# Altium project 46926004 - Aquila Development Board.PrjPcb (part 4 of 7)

## Sheet 360_Ethernet2.SchDoc: Aquila Development Board
size A3; Organization: Toradex Solutions Inc.; Address1: 6415 Northwest Drive; Address2: Mississauga, ON, L4V 1X1; Address3: Canada; SheetNumber: 20; SheetTotal: 34
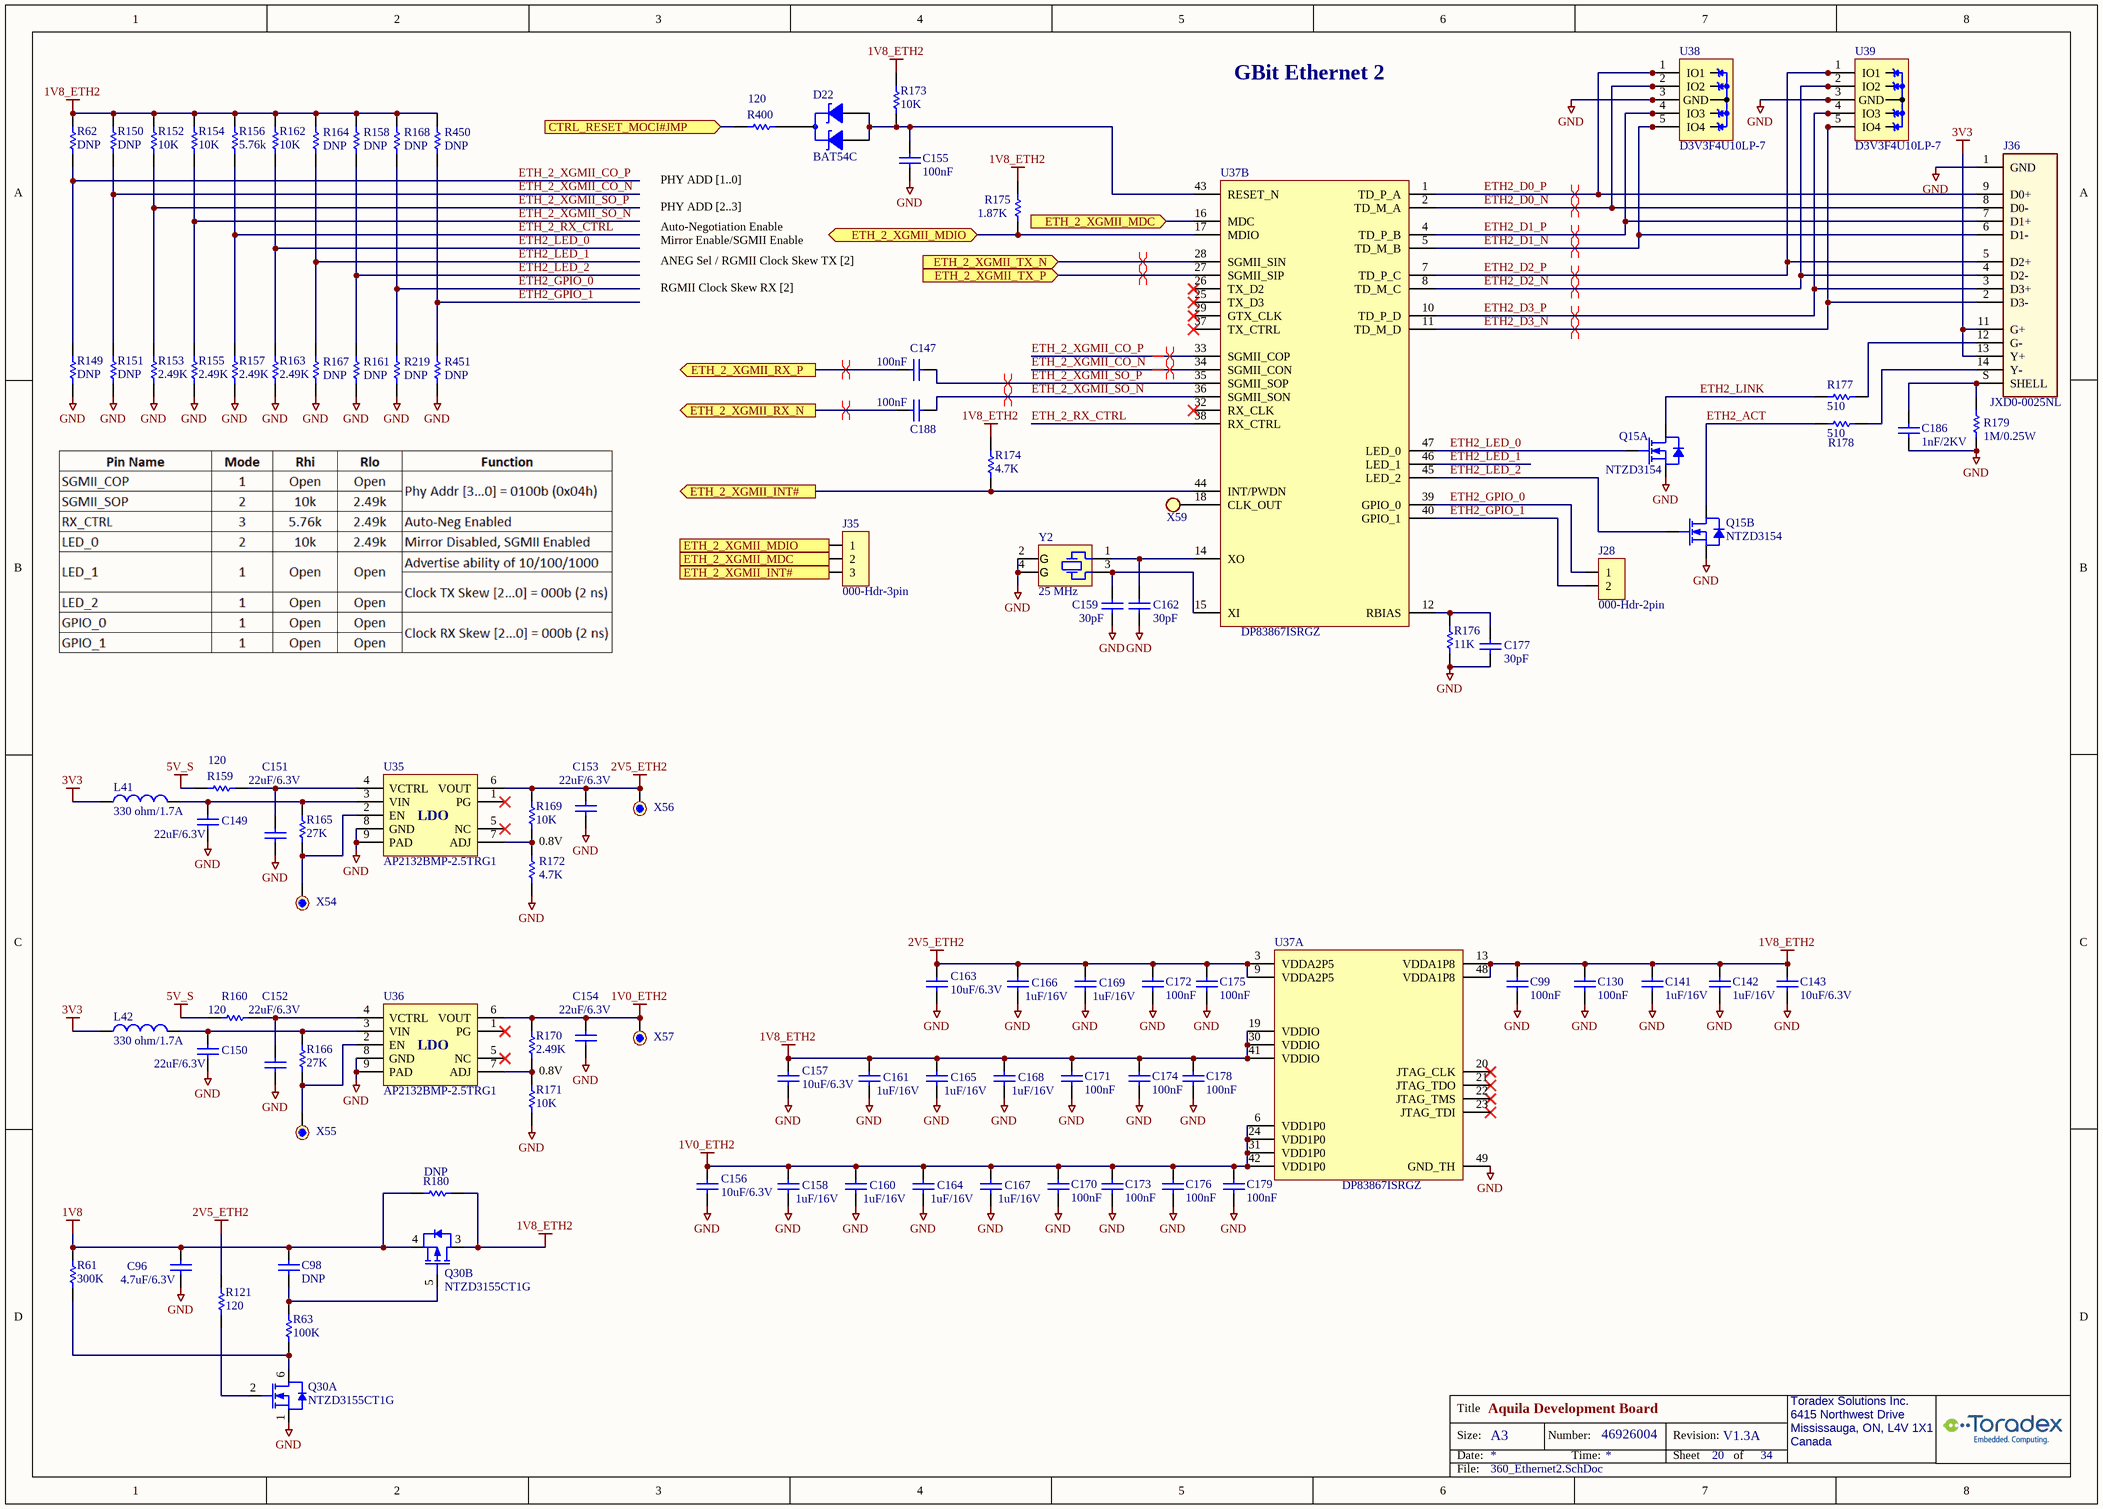
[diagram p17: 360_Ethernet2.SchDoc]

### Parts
C96  value 4.7uF/6.3V  [C0402_CAPC1005L]  (hidden comment: 0354-Cap-0402-4.7uF/6.3V)
C98  value DNP  [C/0603]  (hidden comment: 0000-Cap-0603-DNP)
C99  100nF  [C0402_CAPC1005L]
C130  100nF  [C0402_CAPC1005L]
C141  value 1uF/16V  [C0402_CAPC1005L]  (hidden comment: 1644-Cap-0402-1uF/16V)
C142  value 1uF/16V  [C0402_CAPC1005L]  (hidden comment: 1644-Cap-0402-1uF/16V)
C143  value 10uF/6.3V  [C0402_CAPC1005L]  (hidden comment: 1646-Cap-0402-10uF/6.3V)
C147  100nF  [C0402_CAPC1005L]
C149  22uF/6.3V  [C0402_CAPC1005L]
C150  22uF/6.3V  [C0402_CAPC1005L]
C151  22uF/6.3V  [C0402_CAPC1005L]
C152  22uF/6.3V  [C0402_CAPC1005L]
C153  22uF/6.3V  [C0402_CAPC1005L]
C154  22uF/6.3V  [C0402_CAPC1005L]
C155  100nF  [C0402_CAPC1005L]
C156  value 10uF/6.3V  [C0402_CAPC1005L]  (hidden comment: 1646-Cap-0402-10uF/6.3V)
C157  value 10uF/6.3V  [C0402_CAPC1005L]  (hidden comment: 1646-Cap-0402-10uF/6.3V)
C158  value 1uF/16V  [C0402_CAPC1005L]  (hidden comment: 1644-Cap-0402-1uF/16V)
C159  value 30pF  [C0402_CAPC1005L]  (hidden comment: 1554-Cap-0402-30pF)
C160  value 1uF/16V  [C0402_CAPC1005L]  (hidden comment: 1644-Cap-0402-1uF/16V)
C161  value 1uF/16V  [C0402_CAPC1005L]  (hidden comment: 1644-Cap-0402-1uF/16V)
C162  value 30pF  [C0402_CAPC1005L]  (hidden comment: 1554-Cap-0402-30pF)
C163  value 10uF/6.3V  [C0402_CAPC1005L]  (hidden comment: 1646-Cap-0402-10uF/6.3V)
C164  value 1uF/16V  [C0402_CAPC1005L]  (hidden comment: 1644-Cap-0402-1uF/16V)
C165  value 1uF/16V  [C0402_CAPC1005L]  (hidden comment: 1644-Cap-0402-1uF/16V)
C166  value 1uF/16V  [C0402_CAPC1005L]  (hidden comment: 1644-Cap-0402-1uF/16V)
C167  value 1uF/16V  [C0402_CAPC1005L]  (hidden comment: 1644-Cap-0402-1uF/16V)
C168  value 1uF/16V  [C0402_CAPC1005L]  (hidden comment: 1644-Cap-0402-1uF/16V)
C169  value 1uF/16V  [C0402_CAPC1005L]  (hidden comment: 1644-Cap-0402-1uF/16V)
C170  100nF  [C0402_CAPC1005L]
C171  100nF  [C0402_CAPC1005L]
C172  100nF  [C0402_CAPC1005L]
C173  100nF  [C0402_CAPC1005L]
C174  100nF  [C0402_CAPC1005L]
C175  100nF  [C0402_CAPC1005L]
C176  100nF  [C0402_CAPC1005L]
C177  value 30pF  [C0402_CAPC1005L]  (hidden comment: 1554-Cap-0402-30pF)
C178  100nF  [C0402_CAPC1005L]
C179  100nF  [C0402_CAPC1005L]
C186  value 1nF/2KV  [C/1206]  (hidden comment: 0567-Cap-1206-1nF/2KV)
C188  100nF  [C0402_CAPC1005L]
D22  BAT54C  [SOT23_M]
J28  000-Hdr-2pin  [HDR1X2]  (no BOM)
J35  000-Hdr-3pin  [HDR1X3]  (no BOM)
J36  JXD0-0025NL  [PULSE_JXD0-0025NL]
L41  value 330 ohm/1.7A  [C/0603]  (hidden comment: 0405-Fer-0603-330ohm/1.7A)
L42  value 330 ohm/1.7A  [C/0603]  (hidden comment: 0405-Fer-0603-330ohm/1.7A)
Q15  NTZD3154  [SOT563]  (parts A,B of 2)
Q30  NTZD3155CT1G  [SOTFL50P160X60-6N]  (parts A,B of 2)
R61  value 300K  [R/0603]  (hidden comment: 0176-Res-0603-300K)
R62  value DNP  [R0402_RESC1005L]  (hidden comment: 0000-Res-0402-DNP)
R63  value 100K  [R0402_RESC1005L]  (hidden comment: 1977-Res-0402-100K)
R121  value 120  [R0402_RESC1005L]  (hidden comment: 1552-Res-0402-120)
R149  value DNP  [R0402_RESC1005L]  (hidden comment: 0000-Res-0402-DNP)
R150  value DNP  [R0402_RESC1005L]  (hidden comment: 0000-Res-0402-DNP)
R151  value DNP  [R0402_RESC1005L]  (hidden comment: 0000-Res-0402-DNP)
R152  value 10K  [R0402_RESC1005L]  (hidden comment: 1572-Res-0402-10K)
R153  value 2.49K  [R0402_RESC1005L]  (hidden comment: 2313-Res-0402-2.49K)
R154  value 10K  [R0402_RESC1005L]  (hidden comment: 1572-Res-0402-10K)
R155  value 2.49K  [R0402_RESC1005L]  (hidden comment: 2313-Res-0402-2.49K)
R156  value 5.76k  [R0402_RESC1005L]  (hidden comment: 2077-Res-0402-5.76K)
R157  value 2.49K  [R0402_RESC1005L]  (hidden comment: 2313-Res-0402-2.49K)
R158  value DNP  [R0402_RESC1005L]  (hidden comment: 0000-Res-0402-DNP)
R159  value 120  [R0402_RESC1005L]  (hidden comment: 1552-Res-0402-120)
R160  value 120  [R0402_RESC1005L]  (hidden comment: 1552-Res-0402-120)
R161  value DNP  [R0402_RESC1005L]  (hidden comment: 0000-Res-0402-DNP)
R162  value 10K  [R0402_RESC1005L]  (hidden comment: 1572-Res-0402-10K)
R163  value 2.49K  [R0402_RESC1005L]  (hidden comment: 2313-Res-0402-2.49K)
R164  value DNP  [R0402_RESC1005L]  (hidden comment: 0000-Res-0402-DNP)
R165  value 27K  [R0402_RESC1005L]  (hidden comment: 1538-Res-0402-27k)
R166  value 27K  [R0402_RESC1005L]  (hidden comment: 1538-Res-0402-27k)
R167  value DNP  [R0402_RESC1005L]  (hidden comment: 0000-Res-0402-DNP)
R168  value DNP  [R0402_RESC1005L]  (hidden comment: 0000-Res-0402-DNP)
R169  value 10K  [R0402_RESC1005L]  (hidden comment: 1572-Res-0402-10K)
R170  value 2.49K  [R0402_RESC1005L]  (hidden comment: 2313-Res-0402-2.49K)
R171  value 10K  [R0402_RESC1005L]  (hidden comment: 1572-Res-0402-10K)
R172  value 4.7K  [R0402_RESC1005L]  (hidden comment: 2233-Res-0402-4.7K)
R173  value 10K  [R0402_RESC1005L]  (hidden comment: 1572-Res-0402-10K)
R174  value 4.7K  [R0402_RESC1005L]  (hidden comment: 2233-Res-0402-4.7K)
R175  value 1.87K  [R0402_RESC1005L]  (hidden comment: 1536-Res-0402-1.87K)
R176  value 11K  [R0402_RESC1005L]  (hidden comment: 2527-Res-0402-11K)
R177  value 510  [R/0603]  (hidden comment: 0043-Res-0603-510ohm)
R178  value 510  [R/0603]  (hidden comment: 0043-Res-0603-510ohm)
R179  value 1M/0.25W  [R/1206]  (hidden comment: 1860-Res-1206-1M-5%-0.25W)
R180  value DNP  [R/0603]  (hidden comment: 0000-Res-0603-DNP)
R219  value DNP  [R0402_RESC1005L]  (hidden comment: 0000-Res-0402-DNP)
R400  value 120  [R0402_RESC1005L]  (hidden comment: 1552-Res-0402-120)
R450  value DNP  [R0402_RESC1005L]  (hidden comment: 0000-Res-0402-DNP)
R451  value DNP  [R0402_RESC1005L]  (hidden comment: 0000-Res-0402-DNP)
U35  AP2132BMP-2.5TRG1  [SOP-9 TP_ALT]
U36  AP2132BMP-2.5TRG1  [SOP-9 TP_ALT]
U37  DP83867ISRGZ  [RGZ0048B]  (parts A,B of 2)
U38  D3V3F4U10LP-7  [10-UFDFN]
U39  D3V3F4U10LP-7  [10-UFDFN]
X54  000-TestPoint  [TestPoint_1]  (value not drawn)
X55  000-TestPoint  [TestPoint_1]  (value not drawn)
X56  000-TestPoint  [TestPoint_1]  (value not drawn)
X57  000-TestPoint  [TestPoint_1]  (value not drawn)
X59  000-TestPoint2  [TestPoint_3]  (value not drawn)
Y2  value 25 MHz  [XTAL_CX3225]  (hidden comment: 0987-Xtal 25MHz 3.2x2.5mm)

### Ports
CTRL_RESET_MOCI#JMP (in), ETH_2_XGMII_INT#, ETH_2_XGMII_INT# (out), ETH_2_XGMII_MDC, ETH_2_XGMII_MDC (in), ETH_2_XGMII_MDIO, ETH_2_XGMII_MDIO (bidir), ETH_2_XGMII_RX_N (out), ETH_2_XGMII_RX_P (out), ETH_2_XGMII_TX_N (in), ETH_2_XGMII_TX_P (in)

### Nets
1V0_ETH2: C154.2 C156.2 C158.2 C160.2 C164.2 C167.2 C170.1 C173.1 C176.1 C179.1 R170.2 U36.6(VOUT) U37.6(VDD1P0) U37.24(VDD1P0) U37.31(VDD1P0) U37.42(VDD1P0) X57.1
1V8: C96.2 C98.1 Q30.4(S) R61.1 R180.2
1V8_ETH2: C99.1 C130.1 C141.2 C142.2 C143.2 C157.2 C161.2 C165.2 C168.2 C171.1 C174.1 C178.1 Q30.3(D) R62.2 R150.2 R152.2 R154.2 R156.1 R158.2 R162.2 R164.2 R168.2 R173.2 R174.2 R175.2 R180.1 R450.2 U37.13(VDDA1P8) U37.19(VDDIO) U37.30(VDDIO) U37.41(VDDIO) U37.48(VDDA1P8)
2V5_ETH2: C153.2 C163.2 C166.2 C169.2 C172.1 C175.1 R121.2 R169.2 U35.6(VOUT) U37.3(VDDA2P5) U37.9(VDDA2P5) X56.1
3V3: J36.11(G+) J36.13(Y+) L41.2 L42.2
5V_S: R159.2 R160.2
GND: C96.1 C99.2 C130.2 C141.1 C142.1 C143.1 C149.1 C150.1 C151.1 C152.1 C153.1 C154.1 C155.2 C156.1 C157.1 C158.1 C159.2 C160.1 C161.1 C162.2 C163.1 C164.1 C165.1 C166.1 C167.1 C168.1 C169.1 C170.2 C171.2 C172.2 C173.2 C174.2 C175.2 C176.2 C177.2 C178.2 C179.2 C186.1 J36.1(GND) Q15.1(S) Q15.4(S) Q30.1(S) R149.1 R151.1 R153.1 R155.1 R157.1 R161.1 R163.1 R167.1 R171.1 R172.1 R176.1 R179.2 R219.1 R451.1 U35.8(GND) U35.9(PAD) U36.8(GND) U36.9(PAD) U37.49(GND_TH) U38.3(GND) U38.8(GND) U39.3(GND) U39.8(GND) Y2.2(GND) Y2.4(GND)
CTRL_RESET_MOCI#JMP: R400.2 ; port CTRL_RESET_MOCI#JMP
ETH2_ACT: Q15.3(D) R178.1
ETH2_D0_N: J36.8(D0-) U37.2(TD_M_A) U38.2(IO2) U38.9(NC)
ETH2_D0_P: J36.9(D0+) U37.1(TD_P_A) U38.1(IO1) U38.10(NC)
ETH2_D1_N: J36.6(D1-) U37.5(TD_M_B) U38.5(IO4) U38.6(NC)
ETH2_D1_P: J36.7(D1+) U37.4(TD_P_B) U38.4(IO3) U38.7(NC)
ETH2_D2_N: J36.4(D2-) U37.8(TD_M_C) U39.2(IO2) U39.9(NC)
ETH2_D2_P: J36.5(D2+) U37.7(TD_P_C) U39.1(IO1) U39.10(NC)
ETH2_D3_N: J36.2(D3-) U37.11(TD_M_D) U39.5(IO4) U39.6(NC)
ETH2_D3_P: J36.3(D3+) U37.10(TD_P_D) U39.4(IO3) U39.7(NC)
ETH2_GPIO_0: J28.1 R168.1 R219.2 U37.39(GPIO_0)
ETH2_GPIO_1: J28.2 R450.1 R451.2 U37.40(GPIO_1)
ETH2_LED_0: Q15.2(G) R162.1 R163.2 U37.47(LED_0)
ETH2_LED_1: R164.1 R167.2 U37.46(LED_1)
ETH2_LED_2: Q15.5(G) R158.1 R161.2 U37.45(LED_2)
ETH2_LINK: Q15.6(D) R177.1
ETH_2_RX_CTRL: R156.2 R157.2 U37.38(RX_CTRL)
ETH_2_XGMII_CO_N: R150.1 R151.2 U37.34(SGMII_CON)
ETH_2_XGMII_CO_P: R62.1 R149.2 U37.33(SGMII_COP)
ETH_2_XGMII_INT#: J35.3 R174.1 U37.44(INT/PWDN) ; port ETH_2_XGMII_INT#
ETH_2_XGMII_MDC: J35.2 U37.16(MDC) ; port ETH_2_XGMII_MDC
ETH_2_XGMII_MDIO: J35.1 R175.1 U37.17(MDIO) ; port ETH_2_XGMII_MDIO
ETH_2_XGMII_RX_N: C188.2 ; port ETH_2_XGMII_RX_N
ETH_2_XGMII_RX_P: C147.2 ; port ETH_2_XGMII_RX_P
ETH_2_XGMII_SO_N: C188.1 R154.1 R155.2 U37.36(SGMII_SON)
ETH_2_XGMII_SO_P: C147.1 R152.1 R153.2 U37.35(SGMII_SOP)
ETH_2_XGMII_TX_N: U37.28(SGMII_SIN) ; port ETH_2_XGMII_TX_N
ETH_2_XGMII_TX_P: U37.27(SGMII_SIP) ; port ETH_2_XGMII_TX_P
NetC98_2: C98.2 Q30.5(G) R63.1
NetC149_2: C149.2 L41.1 R165.1 U35.3(VIN)
NetC150_2: C150.2 L42.1 R166.1 U36.3(VIN)
NetC151_2: C151.2 R159.1 U35.4(VCTRL)
NetC152_2: C152.2 R160.1 U36.4(VCTRL)
NetC155_1: C155.1 D22.1(A1) D22.2(A2) R173.1 U37.43(RESET_N)
NetC159_1: C159.1 U37.15(XI) Y2.3
NetC162_1: C162.1 U37.14(XO) Y2.1
NetC177_1: C177.1 R176.2 U37.12(RBIAS)
NetC186_2: C186.2 J36.S(SHELL) R179.1
NetD22_3: D22.3(K) R400.1
NetJ36_12: J36.12(G-) R177.2
NetJ36_14: J36.14(Y-) R178.2
NetQ30_2: Q30.2(G) R121.1
NetQ30_6: Q30.6(D) R61.2 R63.2
NetR165_2: R165.2 U35.2(EN) X54.1
NetR166_2: R166.2 U36.2(EN) X55.1
NetR169_1: R169.1 R172.2 U35.7(ADJ)
NetR170_1: R170.1 R171.2 U36.7(ADJ)
NetU37_18: U37.18(CLK_OUT) X59.1

Not connected (* = marked no-connect by the designer): U35 1(PG)* 5(NC)*; U36 1(PG)* 5(NC)*; U37 20(JTAG_CLK)* 21(JTAG_TDO)* 22(JTAG_TMS)* 23(JTAG_TDI)* 25(TX_D3)* 26(TX_D2)* 29(GTX_CLK)* 32(RX_CLK)* 37(TX_CTRL)*

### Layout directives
differential pair; differential pair class ETH2: ETH2_D0_N, ETH2_D0_P, ETH2_D1_N, ETH2_D1_P, ETH2_D2_N, ETH2_D2_P, ETH2_D3_N, ETH2_D3_P
differential pair; differential pair class XGMII: ETH_2_XGMII_RX_N, ETH_2_XGMII_RX_P, ETH_2_XGMII_TX_N, ETH_2_XGMII_TX_P
differential pair; differential pair class XGMII_PHY: ETH_2_XGMII_CO_N, ETH_2_XGMII_CO_P, ETH_2_XGMII_SO_N, ETH_2_XGMII_SO_P

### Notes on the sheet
- GBit Ethernet 2
- (near R400) PHY ADD [1..0]
- PHY ADD [2..3]
- Auto-Negotiation Enable
- Mirror Enable/SGMII Enable
- ANEG Sel / RGMII Clock Skew TX [2]
- RGMII Clock Skew RX [2]
- 0.8V

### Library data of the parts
C96 = 0354-Cap-0402-4.7uF/6.3V: (-55 to 85 DegC) CAP CER 4.7UF 6.3V 20% X5R 0402; Mfr: Murata Electronics North America; MfrNo: GRM155R60J475ME87D; Alt: 1276-1483-1-ND; Alt2: 490-5915-1-ND; PN: 354
C98 = 0000-Cap-0603-DNP: Cap 0603 DNP
C99 C130 C147 C155 C170-C176 C178 C179 C188 = 1566-Cap-0402-100nF/50V: (-55 to 125 DegC AEC) Cap Ceramic 0.1uF 50V X7R 10% 0402; MfrNo: GRT155R71H104KE01D; Mfr: Murata; Alt: CL05B104KB54PNC,GCM155R71H104ME02D,GCM155R71H104KE02D,GCM155R71H104KE02J; PN: 1566
C141 C142 C158 C160 C161 C164-C169 = 1644-Cap-0402-1uF/16V: (-55 to 85 DegC) CAP CER 1UF 16V 20% X5R 0402; Mfr: Murata; MfrNo: GRM155R61C105MA12D; PN: 1644; Alt: GRM155R61C105KA12D,CL05A105KO5NNNC
C143 C156 C157 C163 = 1646-Cap-0402-10uF/6.3V: (-55 to 85 DegC) CAP CER 10UF 6.3V 20% X5R 0402; Mfr: Murata; MfrNo: GRM155R60J106ME44D; PN: 1646; Alt: GRM155R60J106ME47D,C0402C106M9PACTU,04026D106MAT2A
C149-C154 = 2404-Cap-0402-22uF/6.3V: (-55 to 85 DegC) CAP CER 22UF 6.3V 20% X5R 0402; MfrNo: GRM155R60J226ME11D; Mfr: Murata; PN: 2404
C159 C162 C177 = 1554-Cap-0402-30pF: (-55 to 125 DegC AEC) CAP CER 30PF 5% 50V C0G/NPO 0402; Mfr: Murata; MfrNo: GCM1555C1H300JA16D; PN: 1554; Alt: AC0402JRNPO9BN300,GCM1555C1H300GA16D,GCM1555C1H300FA16D
C186 = 0567-Cap-1206-1nF/2KV: (-55 to 125 DegC) CAP CER 1000PF 2KV X7R 1206; Mfr: Johanson Dielectrics Inc.; MfrNo: 202R18W102KV4E; PN: 567; Alt: 478-2956-1-ND; Alt2: 399-4819-1-ND
D22 = 0242B-BAT54C: (-55 to 125 DegC) DIODE SCHOTTKY 30V 200MA SOT23, comm. Cathode; Mfr: ON Semi; MfrNo: BAT54CLT1G; Alt: BAT54CFSCT-ND; Alt2: BAT54C-FDICT-ND; PN: 242; TR: BAT54CLT1GOSTR-ND; DR: BAT54CLT1GOSDKR-ND; DR2: 863-BAT54CLT1G
J28 = 000-Hdr-2pin: Header, 2-Pin; Note: PCB footprint only, no parts to buy or assemble
J35 = 000-Hdr-3pin: Header, 3-Pin; Note: PCB footprint only, no parts to buy or assemble
J36 = 1380-Conn-RJ45-GBe: (-40 to 85 DegC) CONN MAGJACK 1PORT 1000 BASE-T Isolated Taps; Mfr: Pulse; PN: 1380
L41 L42 = 0405-Fer-0603-330ohm/1.7A: (-55 to 125 DegC) FERRITE BEAD 330 OHM 0603 1.7A 80mohm, typ 48mohm; Mfr: TDK Corporation; MfrNo: MPZ1608S331ATA00; PN: 405; TR: 445-5221-2-ND; DR: 445-5221-6-ND; DR2: 810-MPZ1608S331ATA00
Q15 = 1146-NTZD3154NT1G: (-55 to 150 DegC) MOSFET 2N-CH (dual) 20V 0.54A SOT-563 1.6x1.6mm Vth:1V Ron typ:400m@4.5V, 500m@2.5V, 700m@1.8V; Mfr: ON Semiconductor; PN: 1146; Alt: NTZD3154NT5G,PMDT290UNE,115
Q30 = 1674-NTZD3155CT1G: (-40 to 85 DegC) MOSFET N/P-CH 20V 0.54/0.43A Vgs:1V SOT-563; Mfr: ON Semiconductor; PN: 1674
R61 = 0176-Res-0603-300K: (-55 to 155 DegC) RES 300K OHM 1/10W 1% 0603 SMD; Mfr: Yageo; MfrNo: RC0603FR-07300KL; Alt: RHM300KCFCT-ND; Alt2: P300KHCT-ND; PN: 176; TR: 311-300KHRTR-ND
R62 R149-R151 R158 R161 R164 R167 R168 R219 R450 R451 = 0000-Res-0402-DNP: RES 0402
R63 = 1977-Res-0402-100K: (-55 to 155 DegC) RES 100K OHM 1/16W 1% 0402 SMD; Mfr: Yageo; MfrNo: RC0402FR-07100KL; PN: 1977
R121 R159 R160 R400 = 1552-Res-0402-120: (-55 to 155 DegC AEC) RES 120 OHM 1% 1/16W 100ppm 0402; MfrNo: RMCF0402FT120R; Mfr: Stackpole Electronics; PN: 1552; Alt: AC0402FR-07120RL,CRGCQ0402F120R
R152 R154 R162 R169 R171 R173 = 1572-Res-0402-10K: (-55 to 155 DegC AEC) RES 10K OHM 1% 1/16W 100ppm 0402; Mfr: Stackpole Electronics; MfrNo: RMCF0402FT10K0; Alt: AC0402FR-0710KL,AC0402FR-1310KL,CRGCQ0402F10K; PN: 1572
R153 R155 R157 R163 R170 = 2313-Res-0402-2.49K: (-55 to 155 DegC) RES SMD 2.49K OHM 1% 1/16W 0402 100ppm; Mfr: Yageo; MfrNo: RC0402FR-072K49L; PN: 2313
R156 = 2077-Res-0402-5.76K: (-55 to 155 DegC) RES 5.76K OHM 1/16W 1% 0402 SMD; Mfr: Stackpole Electronics; MfrNo: RMCF0402FT5K76; PN: 2077
R165 R166 = 1538-Res-0402-27k: (-55 to 155 DegC AEC) RES 27K OHM 1% 1/16W 100ppm 0402; Mfr: Stackpole Electronics; MfrNo: RMCF0402FT27K0; PN: 1538; Alt: AC0402FR-0727KL,CRGCQ0402F27K
R172 R174 = 2233-Res-0402-4.7K: (-55 to 155 DegC) RES 4.70K OHM 1/16W 1% 0402 100ppm; MfrNo: RC0402FR-074K7L; Mfr: Yageo; PN: 2233
R175 = 1536-Res-0402-1.87K: (-55 to 155 DegC AEC) RES 1.87K OHM 1% 1/16W 100ppm 0402; Mfr: Stackpole Electronics; MfrNo: RMCF0402FT1K87; Alt: AC0402FR-071K87L,RK73H1ETTP1871F,ERJ-2RKF1871X; PN: 1536
R176 = 2527-Res-0402-11K: (-55 to 155 DegC AEC) RES SMD 11K OHM 1% 1/16W 0402 100ppm 0402; Mfr: Yageo; MfrNo: AC0402FR-0711KL; PN: 2527
R177 R178 = 0043-Res-0603-510ohm: (-55 to 155 DegC) RES 510 OHM 1/10W 1% 0603 SMD; MfrNo: RC0603FR-07510RL; Mfr: Yageo; PN: 43; TR: 311-510HRTR-ND; Alt: RHM510HCT-ND; Alt2: RMCF0603FT510RCT-ND
R179 = 1860-Res-1206-1M-5%-0.25W: (-55 to 155 DegC) RES SMD 1M OHM 5% 0.25W 10ppm 1206; Mfr: TE Connectivity; MfrNo: CRGCQ1206J1M0; PN: 1860; Alt: RMCF1206JT1M00, RMCF1206JG1M00, CR1206-JW-105ELF
R180 = 0000-Res-0603-DNP: RES 0603
U35 U36 = 1467-AP2132BMP-2.5: (-40 to 85 DegC) IC REG LDO LINEAR POS ADJ 5V 2A 8SO; Mfr: Diodes; PN: 1467; Desc: (-40 to 85 DegC) IC REG BUCK ADJ Sync 5A Vin:3.8 to 40V 100-2200kHz FSS (spread spectrum) MaxDuty:100% SO-8EP; Note: These can be also used with adjust Voltage circuit: AP2132BMP-1.2TRG1, AP2132BMP-1.5TRG1
U37 = 2243-DP83867ISRGZ: (-40 to 85 DegC) 1G PHY Gigabit Ethernet Transceiver with SGMII QFN-48; Mfr: Texas Instruments; MfrNo: DP83867ISRGZR; PN: 2243
U38 U39 = 1463-D3V3F4U10LP: (-55 to 150 DegC) IC TVS DIODE 4ch Vrm:3.3V Vbr:6.2 Vcl:5V@16A 12KV/12KV 0.5pF 10-UFDFN 0.5mm; Mfr: Diodes; PN: 1463; Notes: Similar: PN1317
X54-X57 = 000-TestPoint: TestPoint TH; Note: this is PCB footprint only, no parts to buy or assemble
X59 = 000-TestPoint2: TestPoint SMD; Note: PCB footprint only, no parts to buy or assemble
Y2 = 0987-Xtal 25MHz 3.2x2.5mm: (-40 to 85 DegC) CRYSTAL 25.0MHZ 18PF SMD +-50ppm +-20ppm 3.2x2.5mm; MfrNo: LFXTAL055299REEL; Mfr: IQD Frequency Products; PN: 987; Note: caps: 18pF

## Sheet 410_M2_KeyM.SchDoc: Aquila Development Board
size Letter; Organization: Toradex Solutions Inc.; Address1: 6415 Northwest Drive; Address2: Mississauga, ON, L4V 1X1; Address3: Canada; SheetNumber: 22; SheetTotal: 34
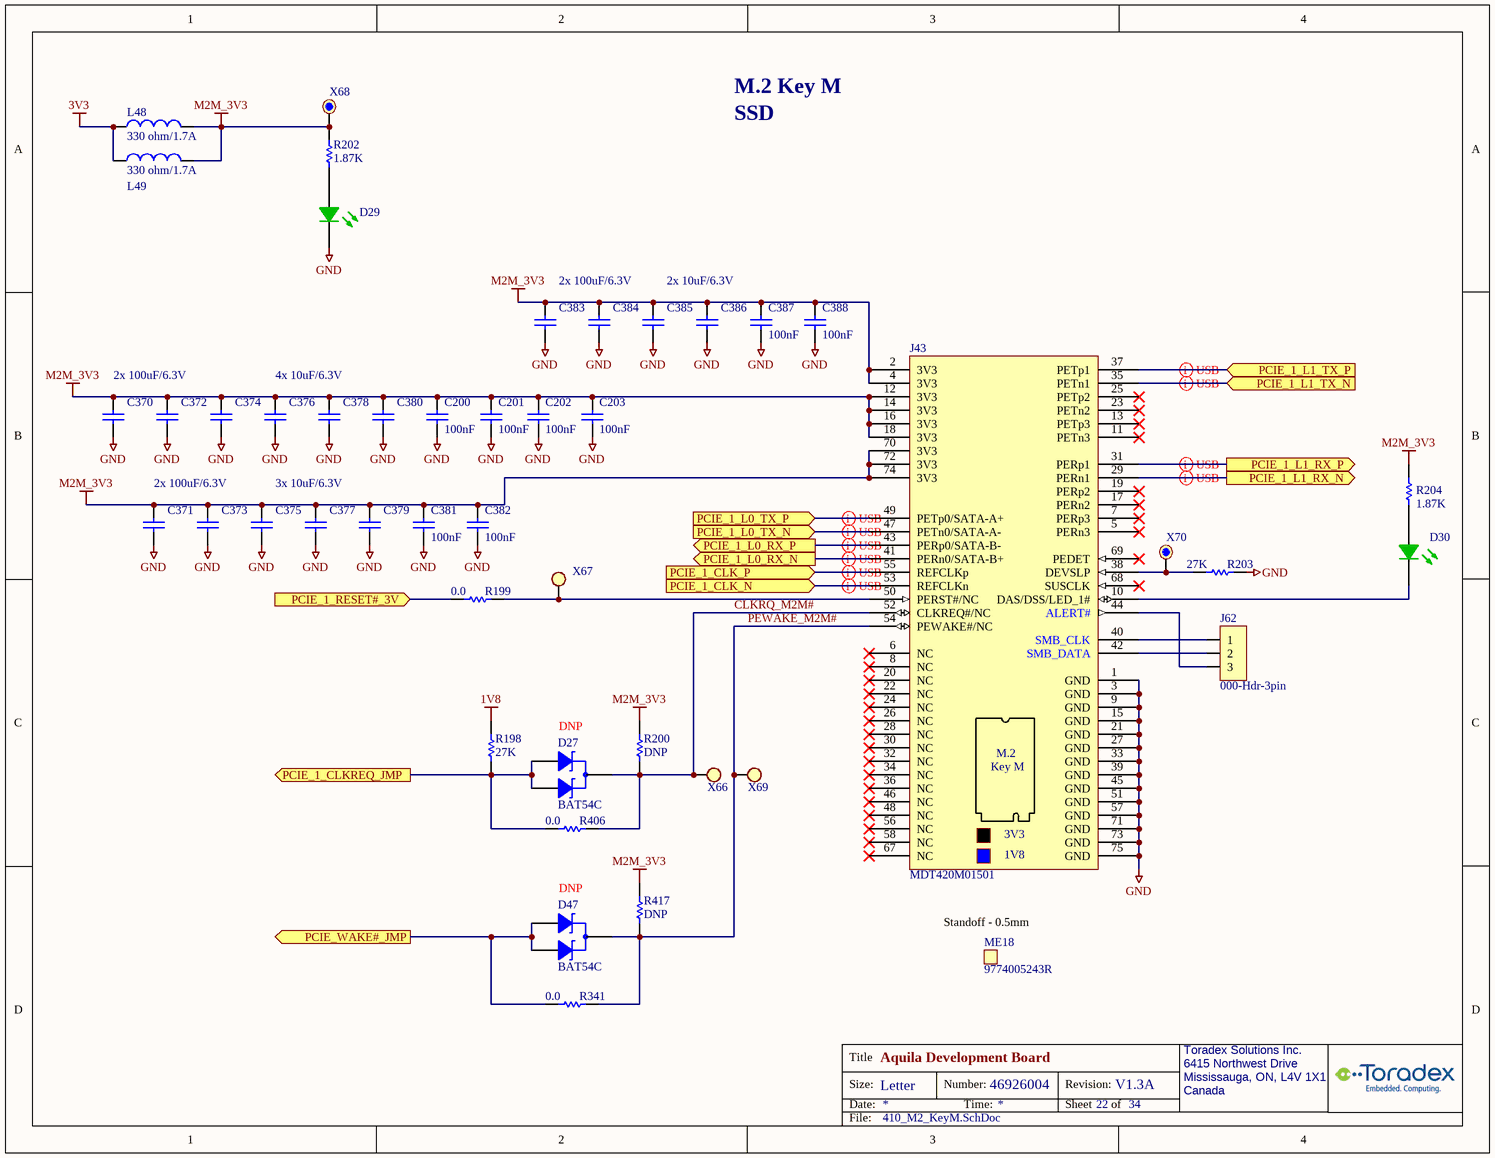
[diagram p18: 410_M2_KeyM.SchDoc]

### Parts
C200  100nF  [C0402_CAPC1005L]
C201  100nF  [C0402_CAPC1005L]
C202  100nF  [C0402_CAPC1005L]
C203  100nF  [C0402_CAPC1005L]
C370  0455-Cap-1206-100uF/6.3V  [C/1206]  (value not drawn)
C371  0455-Cap-1206-100uF/6.3V  [C/1206]  (value not drawn)
C372  0455-Cap-1206-100uF/6.3V  [C/1206]  (value not drawn)
C373  0455-Cap-1206-100uF/6.3V  [C/1206]  (value not drawn)
C374  1646-Cap-0402-10uF/6.3V  [C0402_CAPC1005L]  (value not drawn)
C375  1646-Cap-0402-10uF/6.3V  [C0402_CAPC1005L]  (value not drawn)
C376  1646-Cap-0402-10uF/6.3V  [C0402_CAPC1005L]  (value not drawn)
C377  1646-Cap-0402-10uF/6.3V  [C0402_CAPC1005L]  (value not drawn)
C378  1646-Cap-0402-10uF/6.3V  [C0402_CAPC1005L]  (value not drawn)
C379  1646-Cap-0402-10uF/6.3V  [C0402_CAPC1005L]  (value not drawn)
C380  1646-Cap-0402-10uF/6.3V  [C0402_CAPC1005L]  (value not drawn)
C381  100nF  [C0402_CAPC1005L]
C382  100nF  [C0402_CAPC1005L]
C383  0455-Cap-1206-100uF/6.3V  [C/1206]  (value not drawn)
C384  0455-Cap-1206-100uF/6.3V  [C/1206]  (value not drawn)
C385  1646-Cap-0402-10uF/6.3V  [C0402_CAPC1005L]  (value not drawn)
C386  1646-Cap-0402-10uF/6.3V  [C0402_CAPC1005L]  (value not drawn)
C387  100nF  [C0402_CAPC1005L]
C388  100nF  [C0402_CAPC1005L]
D27  BAT54C  [SOT23_M]  (no BOM)
D29  Status  [LED-SMT-0603_APT1608CGCK]  (value not drawn)
D30  Status  [LED-SMT-0603_APT1608CGCK]  (value not drawn)
D47  BAT54C  [SOT23_M]  (no BOM)
J43  MDT420M01501  [AMPHENOL_MDT420M01501]
J62  000-Hdr-3pin  [HDR1X3]  (no BOM)
L48  value 330 ohm/1.7A  [C/0603]  (hidden comment: 0405-Fer-0603-330ohm/1.7A)
L49  value 330 ohm/1.7A  [C/0603]  (hidden comment: 0405-Fer-0603-330ohm/1.7A)
ME18  9774005243R  [MECH-WURTH-9774005243R]
R198  value 27K  [R0402_RESC1005L]  (hidden comment: 1538-Res-0402-27k)
R199  value 0.0  [R/0603]  (hidden comment: 0195-Res-0603-0.0ohm)
R200  value DNP  [R0402_RESC1005L]  (hidden comment: 0000-Res-0402-DNP)
R202  value 1.87K  [R0402_RESC1005L]  (hidden comment: 1536-Res-0402-1.87K)
R203  value 27K  [R0402_RESC1005L]  (hidden comment: 1538-Res-0402-27k)
R204  value 1.87K  [R0402_RESC1005L]  (hidden comment: 1536-Res-0402-1.87K)
R341  value 0.0  [R/0603]  (hidden comment: 0195-Res-0603-0.0ohm)
R406  value 0.0  [R/0603]  (hidden comment: 0195-Res-0603-0.0ohm)
R417  value DNP  [R0402_RESC1005L]  (hidden comment: 0000-Res-0402-DNP)
X66  000-TestPoint2  [TestPoint_3]  (value not drawn)
X67  000-TestPoint2  [TestPoint_3]  (value not drawn)
X68  000-TestPoint  [TestPoint_1]  (value not drawn)
X69  000-TestPoint2  [TestPoint_3]  (value not drawn)
X70  000-TestPoint  [TestPoint_1]  (value not drawn)

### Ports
PCIE_1_CLK_N (in), PCIE_1_CLK_P (in), PCIE_1_CLKREQ_JMP (out), PCIE_1_L0_RX_N (out), PCIE_1_L0_RX_P (out), PCIE_1_L0_TX_N (in), PCIE_1_L0_TX_P (in), PCIE_1_L1_RX_N (out), PCIE_1_L1_RX_P (out), PCIE_1_L1_TX_N (in), PCIE_1_L1_TX_P (in), PCIE_1_RESET#_3V (in), PCIE_WAKE#_JMP (out)

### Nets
1V8: R198.1
3V3: L48.1 L49.1
GND: C200.1 C201.1 C202.1 C203.1 C370.1 C371.1 C372.1 C373.1 C374.1 C375.1 C376.1 C377.1 C378.1 C379.1 C380.1 C381.1 C382.1 C383.1 C384.1 C385.1 C386.1 C387.1 C388.1 D29.2(K) J43.1(GND) J43.3(GND) J43.9(GND) J43.15(GND) J43.21(GND) J43.27(GND) J43.33(GND) J43.39(GND) J43.45(GND) J43.51(GND) J43.57(GND) J43.71(GND) J43.73(GND) J43.75(GND) R203.2
M2M_3V3: C200.2 C201.2 C202.2 C203.2 C370.2 C371.2 C372.2 C373.2 C374.2 C375.2 C376.2 C377.2 C378.2 C379.2 C380.2 C381.2 C382.2 C383.2 C384.2 C385.2 C386.2 C387.2 C388.2 J43.2(3V3) J43.4(3V3) J43.12(3V3) J43.14(3V3) J43.16(3V3) J43.18(3V3) J43.70(3V3) J43.72(3V3) J43.74(3V3) L48.2 L49.2 R200.2 R202.2 R204.2 R417.1 X68.1
CLKRQ_M2M#: D27.3(K) J43.52(CLKREQ#/NC) R200.1 R406.2 X66.1
PCIE_1_CLK_N: J43.53(REFCLKn) ; port PCIE_1_CLK_N
PCIE_1_CLK_P: J43.55(REFCLKp) ; port PCIE_1_CLK_P
PCIE_1_CLKREQ_JMP: D27.1(A1) D27.2(A2) R198.2 R406.1 ; port PCIE_1_CLKREQ_JMP
PCIE_1_L0_RX_N: J43.41(PERn0/SATA-B+) ; port PCIE_1_L0_RX_N
PCIE_1_L0_RX_P: J43.43(PERp0/SATA-B-) ; port PCIE_1_L0_RX_P
PCIE_1_L0_TX_N: J43.47(PETn0/SATA-A-) ; port PCIE_1_L0_TX_N
PCIE_1_L0_TX_P: J43.49(PETp0/SATA-A+) ; port PCIE_1_L0_TX_P
PCIE_1_L1_RX_N: J43.29(PERn1) ; port PCIE_1_L1_RX_N
PCIE_1_L1_RX_P: J43.31(PERp1) ; port PCIE_1_L1_RX_P
PCIE_1_L1_TX_N: J43.35(PETn1) ; port PCIE_1_L1_TX_N
PCIE_1_L1_TX_P: J43.37(PETp1) ; port PCIE_1_L1_TX_P
PCIE_1_RESET#_3V: R199.1 ; port PCIE_1_RESET#_3V
PCIE_WAKE#_JMP: D47.1(A1) D47.2(A2) R341.1 ; port PCIE_WAKE#_JMP
PEWAKE_M2M#: D47.3(K) J43.54(PEWAKE#/NC) R341.2 R417.2 X69.1
NetD29_1: D29.1(A) R202.1
NetD30_1: D30.1(A) R204.1
NetD30_2: D30.2(K) J43.10(DAS/DSS/LED_1#)
NetJ43_38: J43.38(DEVSLP) R203.1 X70.1
NetJ43_40: J43.40(SMB_CLK) J62.1
NetJ43_42: J43.42(SMB_DATA) J62.2
NetJ43_44: J43.44(ALERT#) J62.3
NetJ43_50: J43.50(PERST#/NC) R199.2 X67.1

Not connected (* = marked no-connect by the designer): J43 5(PERn3)* 6(NC)* 7(PERp3)* 8(NC)* 11(PETn3)* 13(PETp3)* 17(PERn2)* 19(PERp2)* 20(NC)* 22(NC)* 23(PETn2)* 24(NC)* 25(PETp2)* 26(NC)* 28(NC)* 30(NC)* 32(NC)* 34(NC)* 36(NC)* 46(NC)* 48(NC)* 56(NC)* 58(NC)* 67(NC)* 68(SUSCLK)* 69(PEDET)*

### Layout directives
differential pair: PCIE_1_CLK_N, PCIE_1_CLK_P, PCIE_1_L0_RX_N, PCIE_1_L0_RX_P, PCIE_1_L0_TX_N, PCIE_1_L0_TX_P
differential pair; differential pair class PCIe_1: PCIE_1_L1_RX_N, PCIE_1_L1_RX_P, PCIE_1_L1_TX_N, PCIE_1_L1_TX_P

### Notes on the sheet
- M.2 Key M
- SSD
- 2x 100uF/6.3V
- 2x 10uF/6.3V
- 4x 10uF/6.3V
- 3x 10uF/6.3V
- (near D27) DNP
- (near D47) DNP
- (near ME18) Standoff - 0.5mm

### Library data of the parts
C200-C203 C381 C382 C387 C388 = 1566-Cap-0402-100nF/50V: as C99 on sheet 360_Ethernet2
C370-C373 C383 C384 = 0455-Cap-1206-100uF/6.3V: (-55 to 85 DegC) CAP CER 100UF 6.3V X5R 1206; Mfr: Yageo; MfrNo: CC1206MKX5R5BB107; PN: 455; Alt: 490-7217-1-ND; Alt2: 490-4539-1-ND; DR: 311-1991-6-ND; TR: 311-1991-2-ND
C374-C380 C385 C386 = 1646-Cap-0402-10uF/6.3V: as C143 on sheet 360_Ethernet2
D27 D47 = 0242B-BAT54C: as D22 on sheet 360_Ethernet2
D29 D30 = 0333-LED Green 0603: (-40 to 85 DegC) LED GREEN 0603 50mcd; MfrNo: APT1608CGCK; Mfr: Kingbright; Alt: 754-1357-1-ND; Alt2: 160-1834-1-ND; PN: 333; DR: 754-1116-6-ND; DR2: 604-APT1608CGCK
J43 = 2461-Conn-M2-KeyM_4.2mm: (-40 to 85 DegC) CONN M.2 KEYM FMALE 67POS 0.020 GOLD 4.2MM HEIGHT; Mfr: Amphenol Communications Solutions; Desc: (-40 to 85 DegC) CONN M.2 KEYM FMALE 67POS 0.020 GOLD 8.5MM HEIGHT; PN: 2461
J62 = 000-Hdr-3pin: as J35 on sheet 360_Ethernet2
L48 L49 = 0405-Fer-0603-330ohm/1.7A: as L41 on sheet 360_Ethernet2
ME18 = 1855-Post-M2-0.5mm: (-55 to 155 DegC) ROUND STANDOFF M2X0.4 STEEL 0.5MM; Mfr: Wurth Electronics; PN: 1855
R198 R203 = 1538-Res-0402-27k: as R165 on sheet 360_Ethernet2
R199 R341 R406 = 0195-Res-0603-0.0ohm: (-55 to 155 DegC) RES 0.0 OHM 1/10W JUMP 0603; Mfr: Samsung; MfrNo: RC1608J000CS; Alt: 311-0.0GRCT-ND; Alt2: A106051CT-ND; PN: 195; TR: 1276-3510-2-ND
R200 R417 = 0000-Res-0402-DNP: RES 0402
R202 R204 = 1536-Res-0402-1.87K: (-55 to 155 DegC AEC) RES 1.87K OHM 1% 1/16W 100ppm 0402; MfrNo: RMCF0402FT1K87; Mfr: Stackpole Electronics; Alt: AC0402FR-071K87L,RK73H1ETTP1871F,ERJ-2RKF1871X; PN: 1536
X66 X67 X69 = 000-TestPoint2: as X59 on sheet 360_Ethernet2
X68 X70 = 000-TestPoint: as X54-X57 on sheet 360_Ethernet2

## Sheet 540_Audio.SchDoc: Aquila Development Board
size A3; Organization: Toradex Solutions Inc.; Address1: 6415 Northwest Drive; Address2: Mississauga, ON, L4V 1X1; Address3: Canada; SheetNumber: 28; SheetTotal: 34
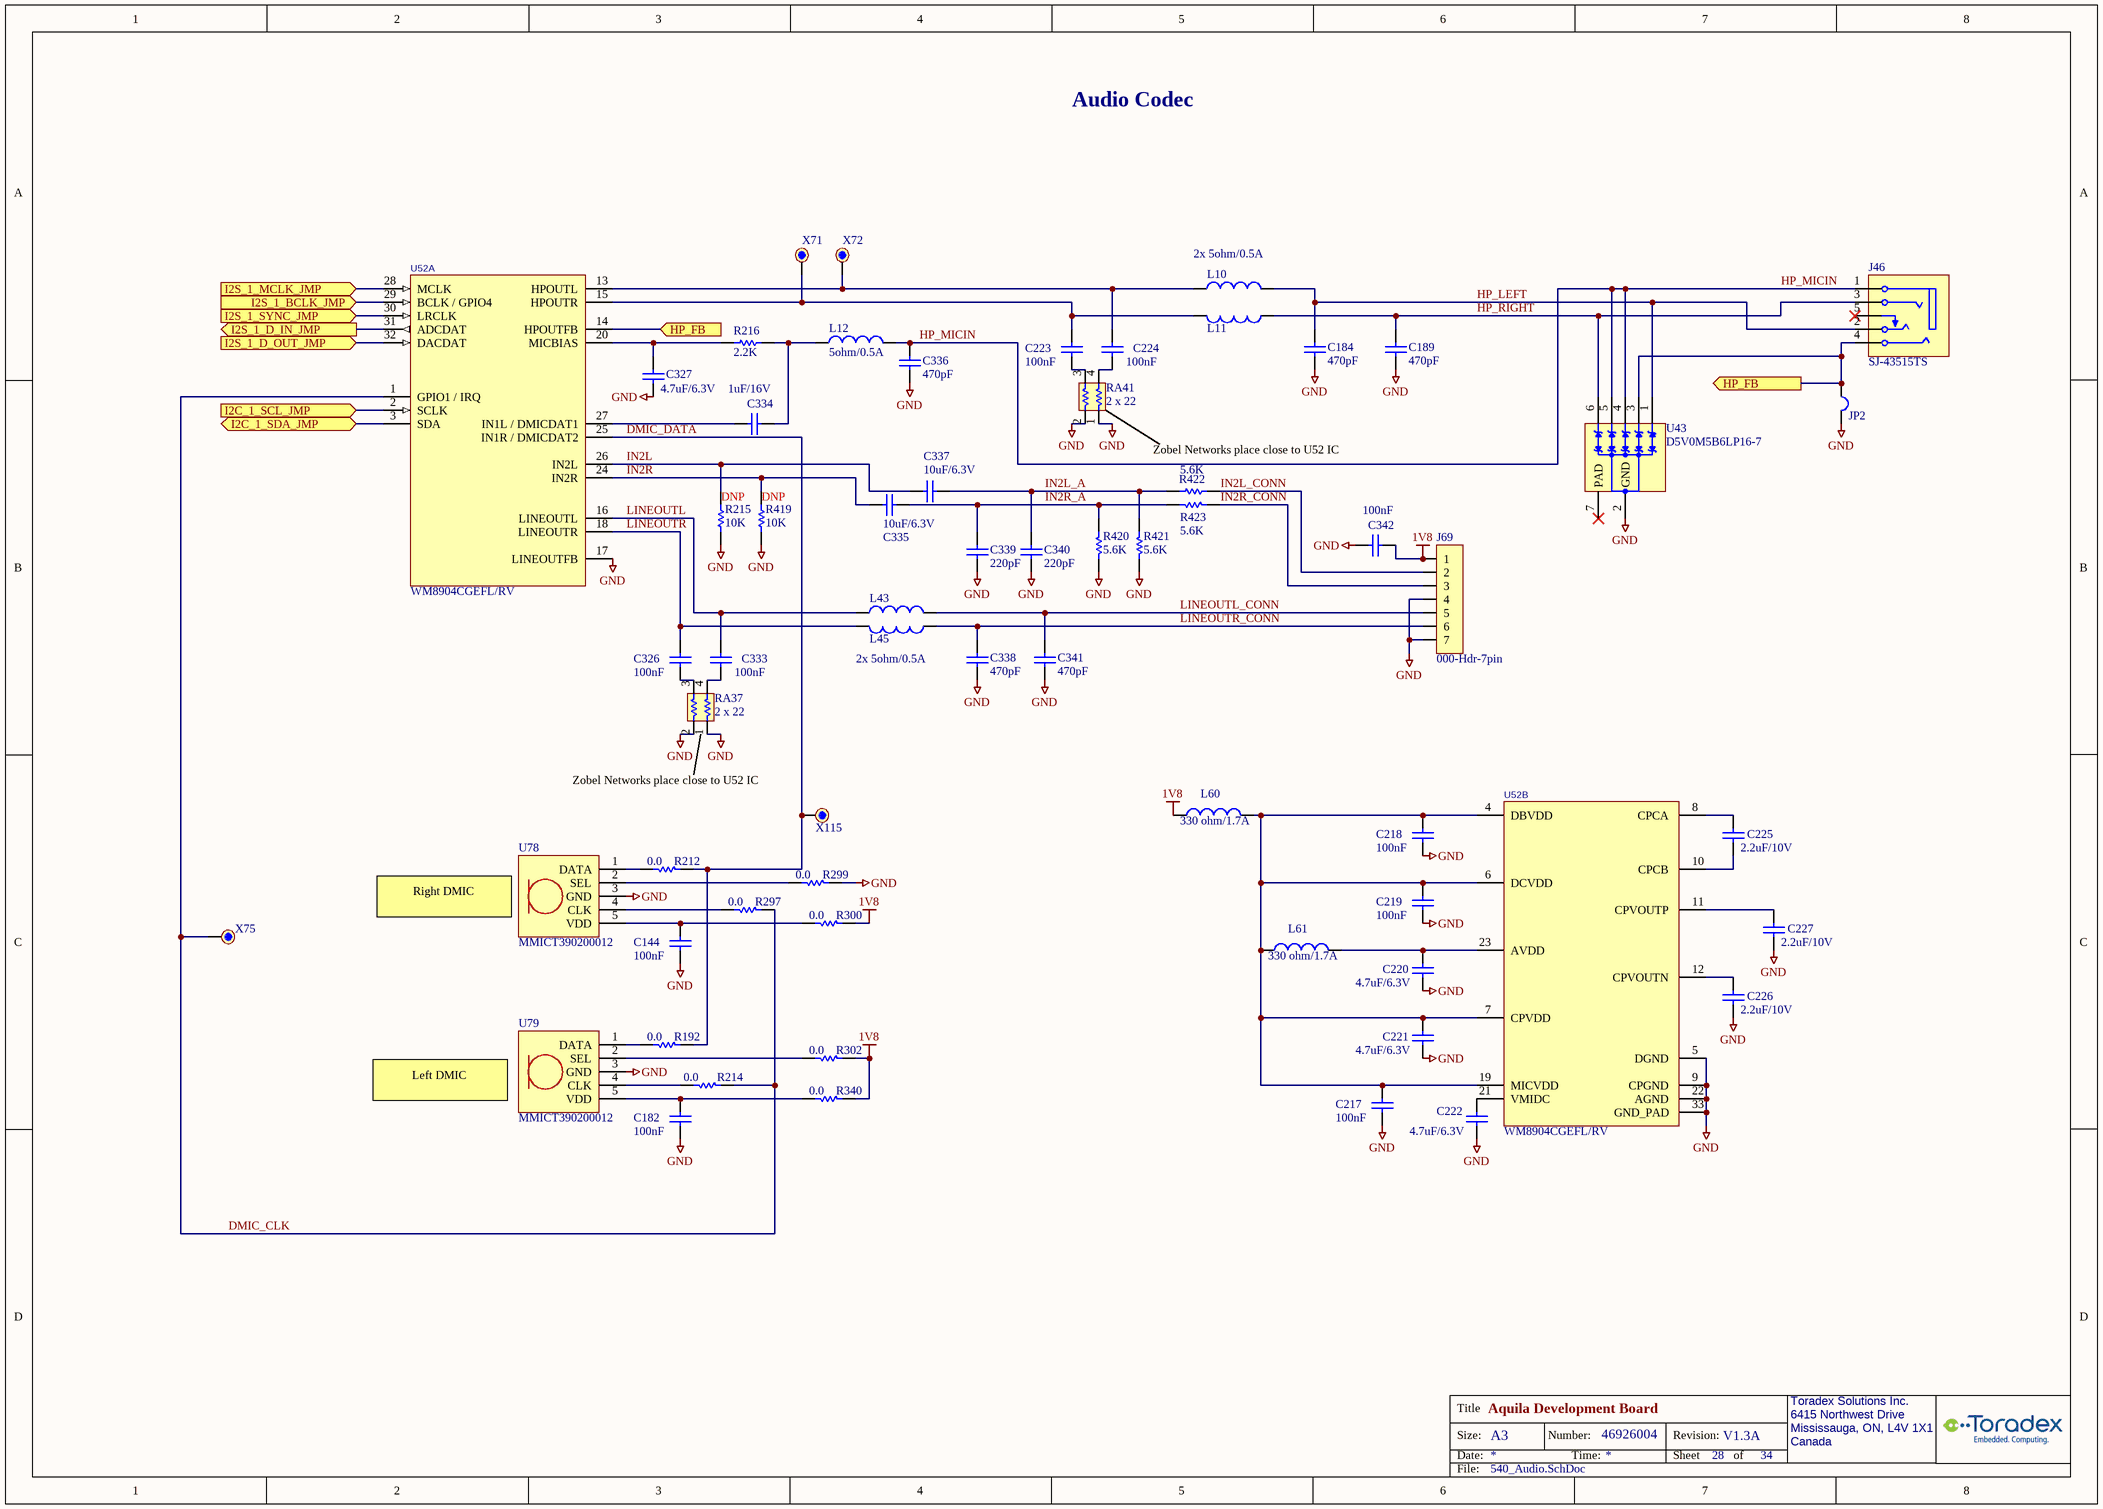
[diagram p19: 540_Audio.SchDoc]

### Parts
C144  100nF  [C0402_CAPC1005L]
C182  100nF  [C0402_CAPC1005L]
C184  value 470pF  [C/0603]  (hidden comment: 0665-Cap-0603-470pF/50V)
C189  value 470pF  [C/0603]  (hidden comment: 0665-Cap-0603-470pF/50V)
C217  100nF  [C0402_CAPC1005L]
C218  100nF  [C0402_CAPC1005L]
C219  100nF  [C0402_CAPC1005L]
C220  value 4.7uF/6.3V  [C0402_CAPC1005L]  (hidden comment: 0354-Cap-0402-4.7uF/6.3V)
C221  value 4.7uF/6.3V  [C0402_CAPC1005L]  (hidden comment: 0354-Cap-0402-4.7uF/6.3V)
C222  value 4.7uF/6.3V  [C0402_CAPC1005L]  (hidden comment: 0354-Cap-0402-4.7uF/6.3V)
C223  100nF  [C0402_CAPC1005L]
C224  100nF  [C0402_CAPC1005L]
C225  value 2.2uF/10V  [C0402_CAPC1005L]  (hidden comment: 2234-Cap-0402-2.2uF/10V)
C226  value 2.2uF/10V  [C0402_CAPC1005L]  (hidden comment: 2234-Cap-0402-2.2uF/10V)
C227  value 2.2uF/10V  [C0402_CAPC1005L]  (hidden comment: 2234-Cap-0402-2.2uF/10V)
C326  100nF  [C0402_CAPC1005L]
C327  value 4.7uF/6.3V  [C0402_CAPC1005L]  (hidden comment: 0354-Cap-0402-4.7uF/6.3V)
C333  100nF  [C0402_CAPC1005L]
C334  value 1uF/16V  [C0402_CAPC1005L]  (hidden comment: 1644-Cap-0402-1uF/16V)
C335  value 10uF/6.3V  [C0402_CAPC1005L]  (hidden comment: 1646-Cap-0402-10uF/6.3V)
C336  value 470pF  [C/0603]  (hidden comment: 0665-Cap-0603-470pF/50V)
C337  value 10uF/6.3V  [C0402_CAPC1005L]  (hidden comment: 1646-Cap-0402-10uF/6.3V)
C338  value 470pF  [C/0603]  (hidden comment: 0665-Cap-0603-470pF/50V)
C339  value 220pF  [C/0603]  (hidden comment: 0213-Cap-0603-220pF/50V)
C340  value 220pF  [C/0603]  (hidden comment: 0213-Cap-0603-220pF/50V)
C341  value 470pF  [C/0603]  (hidden comment: 0665-Cap-0603-470pF/50V)
C342  100nF  [C0402_CAPC1005L]
J46  SJ-43515TS  [CUI_SJ-43515TS]
J69  000-Hdr-7pin  [HDR1X7]  (no BOM)
JP2  Short  [Short_040]  (value not drawn)  (net tie, no BOM)
L10  2247-Fer-0402-5ohm/0.5A  [R0402_RESC1005L]  (value not drawn)
L11  2247-Fer-0402-5ohm/0.5A  [R0402_RESC1005L]  (value not drawn)
L12  value 5ohm/0.5A  [R0402_RESC1005L]  (hidden comment: 2247-Fer-0402-5ohm/0.5A)
L43  2247-Fer-0402-5ohm/0.5A  [R0402_RESC1005L]  (value not drawn)
L45  2247-Fer-0402-5ohm/0.5A  [R0402_RESC1005L]  (value not drawn)
L60  value 330 ohm/1.7A  [C/0603]  (hidden comment: 0405-Fer-0603-330ohm/1.7A)
L61  value 330 ohm/1.7A  [C/0603]  (hidden comment: 0405-Fer-0603-330ohm/1.7A)
R192  value 0.0  [R/0603]  (hidden comment: 0195-Res-0603-0.0ohm)
R212  value 0.0  [R/0603]  (hidden comment: 0195-Res-0603-0.0ohm)
R214  value 0.0  [R/0603]  (hidden comment: 0195-Res-0603-0.0ohm)
R215  value 10K  [R0402_RESC1005L]  (hidden comment: 1572-Res-0402-10K)  (no BOM)
R216  value 2.2K  [R/0603]  (hidden comment: 0045-Res-0603-2.2K)
R297  value 0.0  [R/0603]  (hidden comment: 0195-Res-0603-0.0ohm)
R299  value 0.0  [R/0603]  (hidden comment: 0195-Res-0603-0.0ohm)
R300  value 0.0  [R/0603]  (hidden comment: 0195-Res-0603-0.0ohm)
R302  value 0.0  [R/0603]  (hidden comment: 0195-Res-0603-0.0ohm)
R340  value 0.0  [R/0603]  (hidden comment: 0195-Res-0603-0.0ohm)
R419  value 10K  [R0402_RESC1005L]  (hidden comment: 1572-Res-0402-10K)  (no BOM)
R420  value 5.6K  [R0402_RESC1005L]  (hidden comment: 2254-Res-0402-5.6k)
R421  value 5.6K  [R0402_RESC1005L]  (hidden comment: 2254-Res-0402-5.6k)
R422  value 5.6K  [R0402_RESC1005L]  (hidden comment: 2254-Res-0402-5.6k)
R423  value 5.6K  [R0402_RESC1005L]  (hidden comment: 2254-Res-0402-5.6k)
RA37  value 2 x 22  [EXB34V]  (hidden comment: 1265-ResArr-22ohm)
RA41  value 2 x 22  [EXB34V]  (hidden comment: 1265-ResArr-22ohm)
U43  D5V0M5B6LP16-7  [U-DFN1616-6]
U52  WM8904CGEFL/RV  [QFN40P400X400X75_HS-33N]  (parts A,B of 2)
U78  MMICT390200012  [TDK_MMICT5818-00-012]
U79  MMICT390200012  [TDK_MMICT5818-00-012]
X71  000-TestPoint  [TestPoint_1]  (value not drawn)
X72  000-TestPoint  [TestPoint_1]  (value not drawn)
X75  000-TestPoint  [TestPoint_1]  (value not drawn)
X115  000-TestPoint  [TestPoint_1]  (value not drawn)

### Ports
HP_FB (in), HP_FB (out), I2C_1_SCL_JMP (in), I2C_1_SDA_JMP (bidir), I2S_1_BCLK_JMP (in), I2S_1_D_IN_JMP (out), I2S_1_D_OUT_JMP (in), I2S_1_MCLK_JMP (in), I2S_1_SYNC_JMP (in)

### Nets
1V8: C342.2 J69.1 L60.1 R300.1 R302.1 R340.1
GND: C144.1 C182.1 C184.1 C189.1 C217.1 C218.1 C219.1 C220.1 C221.1 C222.1 C226.1 C227.1 C327.2 C336.1 C338.1 C339.1 C340.1 C341.1 C342.1 J69.4 J69.7 JP2.1(C1) R215.2 R299.1 R419.2 R420.1 R421.1 RA37.1 RA37.2 RA41.1 RA41.2 U43.2(GND) U52.5(DGND) U52.9(CPGND) U52.17(LINEOUTFB) U52.22(AGND) U52.33(GND_PAD) U78.3(GND) U79.3(GND)
DMIC_CLK: R214.1 R297.1 U52.1(GPIO1_/_IRQ) X75.1
DMIC_DATA: R192.1 R212.1 U52.25(IN1R_/_DMICDAT2) X115.1
HP_FB: J46.4 JP2.2(C2) U43.3(IO2) U52.14(HPOUTFB) ; port HP_FB
HP_LEFT: C184.2 J46.2 L10.2 U43.1(IO1)
HP_MICIN: C336.2 J46.1 L12.2 U43.4(GND) U43.5(IO3)
HP_RIGHT: C189.2 J46.3 L11.2 U43.6(IO4)
I2C_1_SCL_JMP: U52.2(SCLK) ; port I2C_1_SCL_JMP
I2C_1_SDA_JMP: U52.3(SDA) ; port I2C_1_SDA_JMP
I2S_1_BCLK_JMP: U52.29(BCLK_/_GPIO4) ; port I2S_1_BCLK_JMP
I2S_1_D_IN_JMP: U52.31(ADCDAT) ; port I2S_1_D_IN_JMP
I2S_1_D_OUT_JMP: U52.32(DACDAT) ; port I2S_1_D_OUT_JMP
I2S_1_MCLK_JMP: U52.28(MCLK) ; port I2S_1_MCLK_JMP
I2S_1_SYNC_JMP: U52.30(LRCLK) ; port I2S_1_SYNC_JMP
IN2L: C337.2 R215.1 U52.26(IN2L)
IN2L_A: C337.1 C340.2 R421.2 R422.1
IN2L_CONN: J69.2 R422.2
IN2R: C335.2 R419.1 U52.24(IN2R)
IN2R_A: C335.1 C339.2 R420.2 R423.1
IN2R_CONN: J69.3 R423.2
LINEOUTL: C333.2 L43.1 U52.16(LINEOUTL)
LINEOUTL_CONN: C341.2 J69.5 L43.2
LINEOUTR: C326.2 L45.1 U52.18(LINEOUTR)
LINEOUTR_CONN: C338.2 J69.6 L45.2
NetC144_2: C144.2 R300.2 U78.5(VDD)
NetC182_2: C182.2 R340.2 U79.5(VDD)
NetC217_2: C217.2 C218.2 C219.2 C221.2 L60.2 L61.1 U52.4(DBVDD) U52.6(DCVDD) U52.7(CPVDD) U52.19(MICVDD)
NetC220_2: C220.2 L61.2 U52.23(AVDD)
NetC222_2: C222.2 U52.21(VMIDC)
NetC223_1: C223.1 RA41.3
NetC223_2: C223.2 L11.1 U52.15(HPOUTR) X71.1
NetC224_1: C224.1 RA41.4
NetC224_2: C224.2 L10.1 U52.13(HPOUTL) X72.1
NetC225_1: C225.1 U52.10(CPCB)
NetC225_2: C225.2 U52.8(CPCA)
NetC226_2: C226.2 U52.12(CPVOUTN)
NetC227_2: C227.2 U52.11(CPVOUTP)
NetC326_1: C326.1 RA37.3
NetC327_1: C327.1 R216.2 U52.20(MICBIAS)
NetC333_1: C333.1 RA37.4
NetC334_1: C334.1 L12.1 R216.1
NetC334_2: C334.2 U52.27(IN1L_/_DMICDAT1)
NetR192_2: R192.2 U79.1(DATA)
NetR212_2: R212.2 U78.1(DATA)
NetR214_2: R214.2 U79.4(CLK)
NetR297_2: R297.2 U78.4(CLK)
NetR299_2: R299.2 U78.2(SEL)
NetR302_2: R302.2 U79.2(SEL)

Not connected (* = marked no-connect by the designer): J46 5*; U43 7(PAD)*

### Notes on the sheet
- Audio Codec
- (near L10) 2x 5ohm/0.5A
- Zobel Networks place close to U52 IC
- (near R215) DNP
- (near R419) DNP
- 2x 5ohm/0.5A
- Right DMIC
- Left DMIC

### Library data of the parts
C144 C182 C217-C219 C223 C224 C326 C333 C342 = 1566-Cap-0402-100nF/50V: as C99 on sheet 360_Ethernet2
C184 C189 C336 C338 C341 = 0665-Cap-0603-470pF/50V: (-55 to 125 DegC) CAP CER 470PF 50V NP0 0603; MfrNo: CL10C471JB8NNNC; Mfr: Samsung Electro-Mechanics America, Inc.; Alt: CL10C471JB8NCNC; PN: 665; DR: 1276-1168-6-ND; TR: 1276-1168-2-ND
C220-C222 = 0354-Cap-0402-4.7uF/6.3V: as C96 on sheet 360_Ethernet2
C225-C227 = 2234-Cap-0402-2.2uF/10V: (-55 to 85 DegC) CAP CER 2.2UF 10V 20% X5R 0402; Mfr: Yageo; MfrNo: CC0402MRX5R6BB225; PN: 2234
C327 = 0354-Cap-0402-4.7uF/6.3V: (-55 to 85 DegC) CAP CER 4.7UF 6.3V 20% X5R 0402; MfrNo: GRM155R60J475ME87D; Mfr: Murata Electronics North America; Alt: 1276-1483-1-ND; PN: 354; Alt2: 490-5915-1-ND
C334 = 1644-Cap-0402-1uF/16V: (-55 to 85 DegC) CAP CER 1UF 16V 20% X5R 0402; Mfr: Murata; MfrNo: GRM155R61C105MA12D; Alt: GRM155R61C105KA12D,CL05A105KO5NNNC; PN: 1644
C335 C337 = 1646-Cap-0402-10uF/6.3V: as C143 on sheet 360_Ethernet2
C339 C340 = 0213-Cap-0603-220pF/50V: (-55 to 125 DegC) CAP CER 220PF 50V 5% NP0 0603; Mfr: Samsung; MfrNo: CL10C221JB8NCNC; Alt: 1276-2231-1-ND; Alt2: 399-1066-1-ND; PN: 213; TR: 1276-2234-2-ND; DR: 1276-2234-6-ND
J46 = 1840-Conn-Audio-Jack-5pos-3.5mm: (-20 to 85 DegC) CONN JACK STEREO 3.5MM 5pos TipSwitch TH R/A; Mfr: Same Sky; PN: 1840
J69 = 000-Hdr-7pin: Header, 7-Pin; Note: PCB footprint only, no parts to buy or assemble
JP2 = 000-Jumper-Short: Jumper Wire
L10-L12 L43 L45 = 2247-Fer-0402-5ohm/0.5A: (-55 to 125 DegC) FERRITE BEAD 5 OHM @ 100MHz 0402 0.5A DCR:80mohm; Mfr: Murata; MfrNo: BLM15BB050SN1D; PN: 2247
L60 L61 = 0405-Fer-0603-330ohm/1.7A: as L41 on sheet 360_Ethernet2
R192 R212 R214 R297 R299 R300 R302 R340 = 0195-Res-0603-0.0ohm: RES 0.0 OHM 1/10W JUMP 0603; Mfr: Samsung; MfrNo: RC1608J000CS; Alt: 311-0.0GRCT-ND; Alt2: A106051CT-ND; PN: 195; TR: 1276-3510-2-ND
R215 R419 = 1572-Res-0402-10K: as R152 on sheet 360_Ethernet2
R216 = 0045-Res-0603-2.2K: (-55 to 155 DegC) RES 2.20K OHM 1/10W 1% 0603 SMD; MfrNo: RC0603FR-072K2L; Mfr: Yageo; Alt: 311-2.2KLDCT-ND; Alt2: RHM2.20KCFCT-ND; PN: 45; TR: 311-2.20KHRTR-ND
R420-R423 = 2254-Res-0402-5.6k: (-55 to 155 DegC AEC) RES 5.6K OHM 1% 1/16W 100ppm 0402; Mfr: Yageo; MfrNo: RC0402FR-075K6L; PN: 2254
RA37 RA41 = 1265-ResArr-22ohm: (-55 to 125 DegC) RES ARRAY 2 RES 22 OHM 5% 0606 200ppm; Mfr: Panasonic; MfrNo: EXB-34V220JV; PN: 1265; Alt: EXB-V4V220JV
U43 = 2248-D5V0M5B6LP16-7: (-65 to 150 DegC) IC TVS DIODE 5ch Vrm:5V Vcl:10V@1A 6-UFDFN; Mfr: Diodes; PN: 2248
U52 = 1498-WM8904: (-40 to 85 DegC) IC AUDIO CODEC STEREO 32QFN; Mfr: Cirrus Logic; PN: 1498
U78 U79 = 2516-T3902: (-40 to 85 DegC) IC MIC Bot Port PDM 3.5x2.6mm 1.65-3.63V; Mfr: TDK InvenSense; PN: 2516
X71 X72 X75 X115 = 000-TestPoint: as X54-X57 on sheet 360_Ethernet2

## Sheet 620_Peripherals2.SchDoc: Aquila Development Board
size A3; Organization: Toradex Solutions Inc.; Address1: 6415 Northwest Drive; Address2: Mississauga, ON, L4V 1X1; Address3: Canada; SheetNumber: 30; SheetTotal: 34
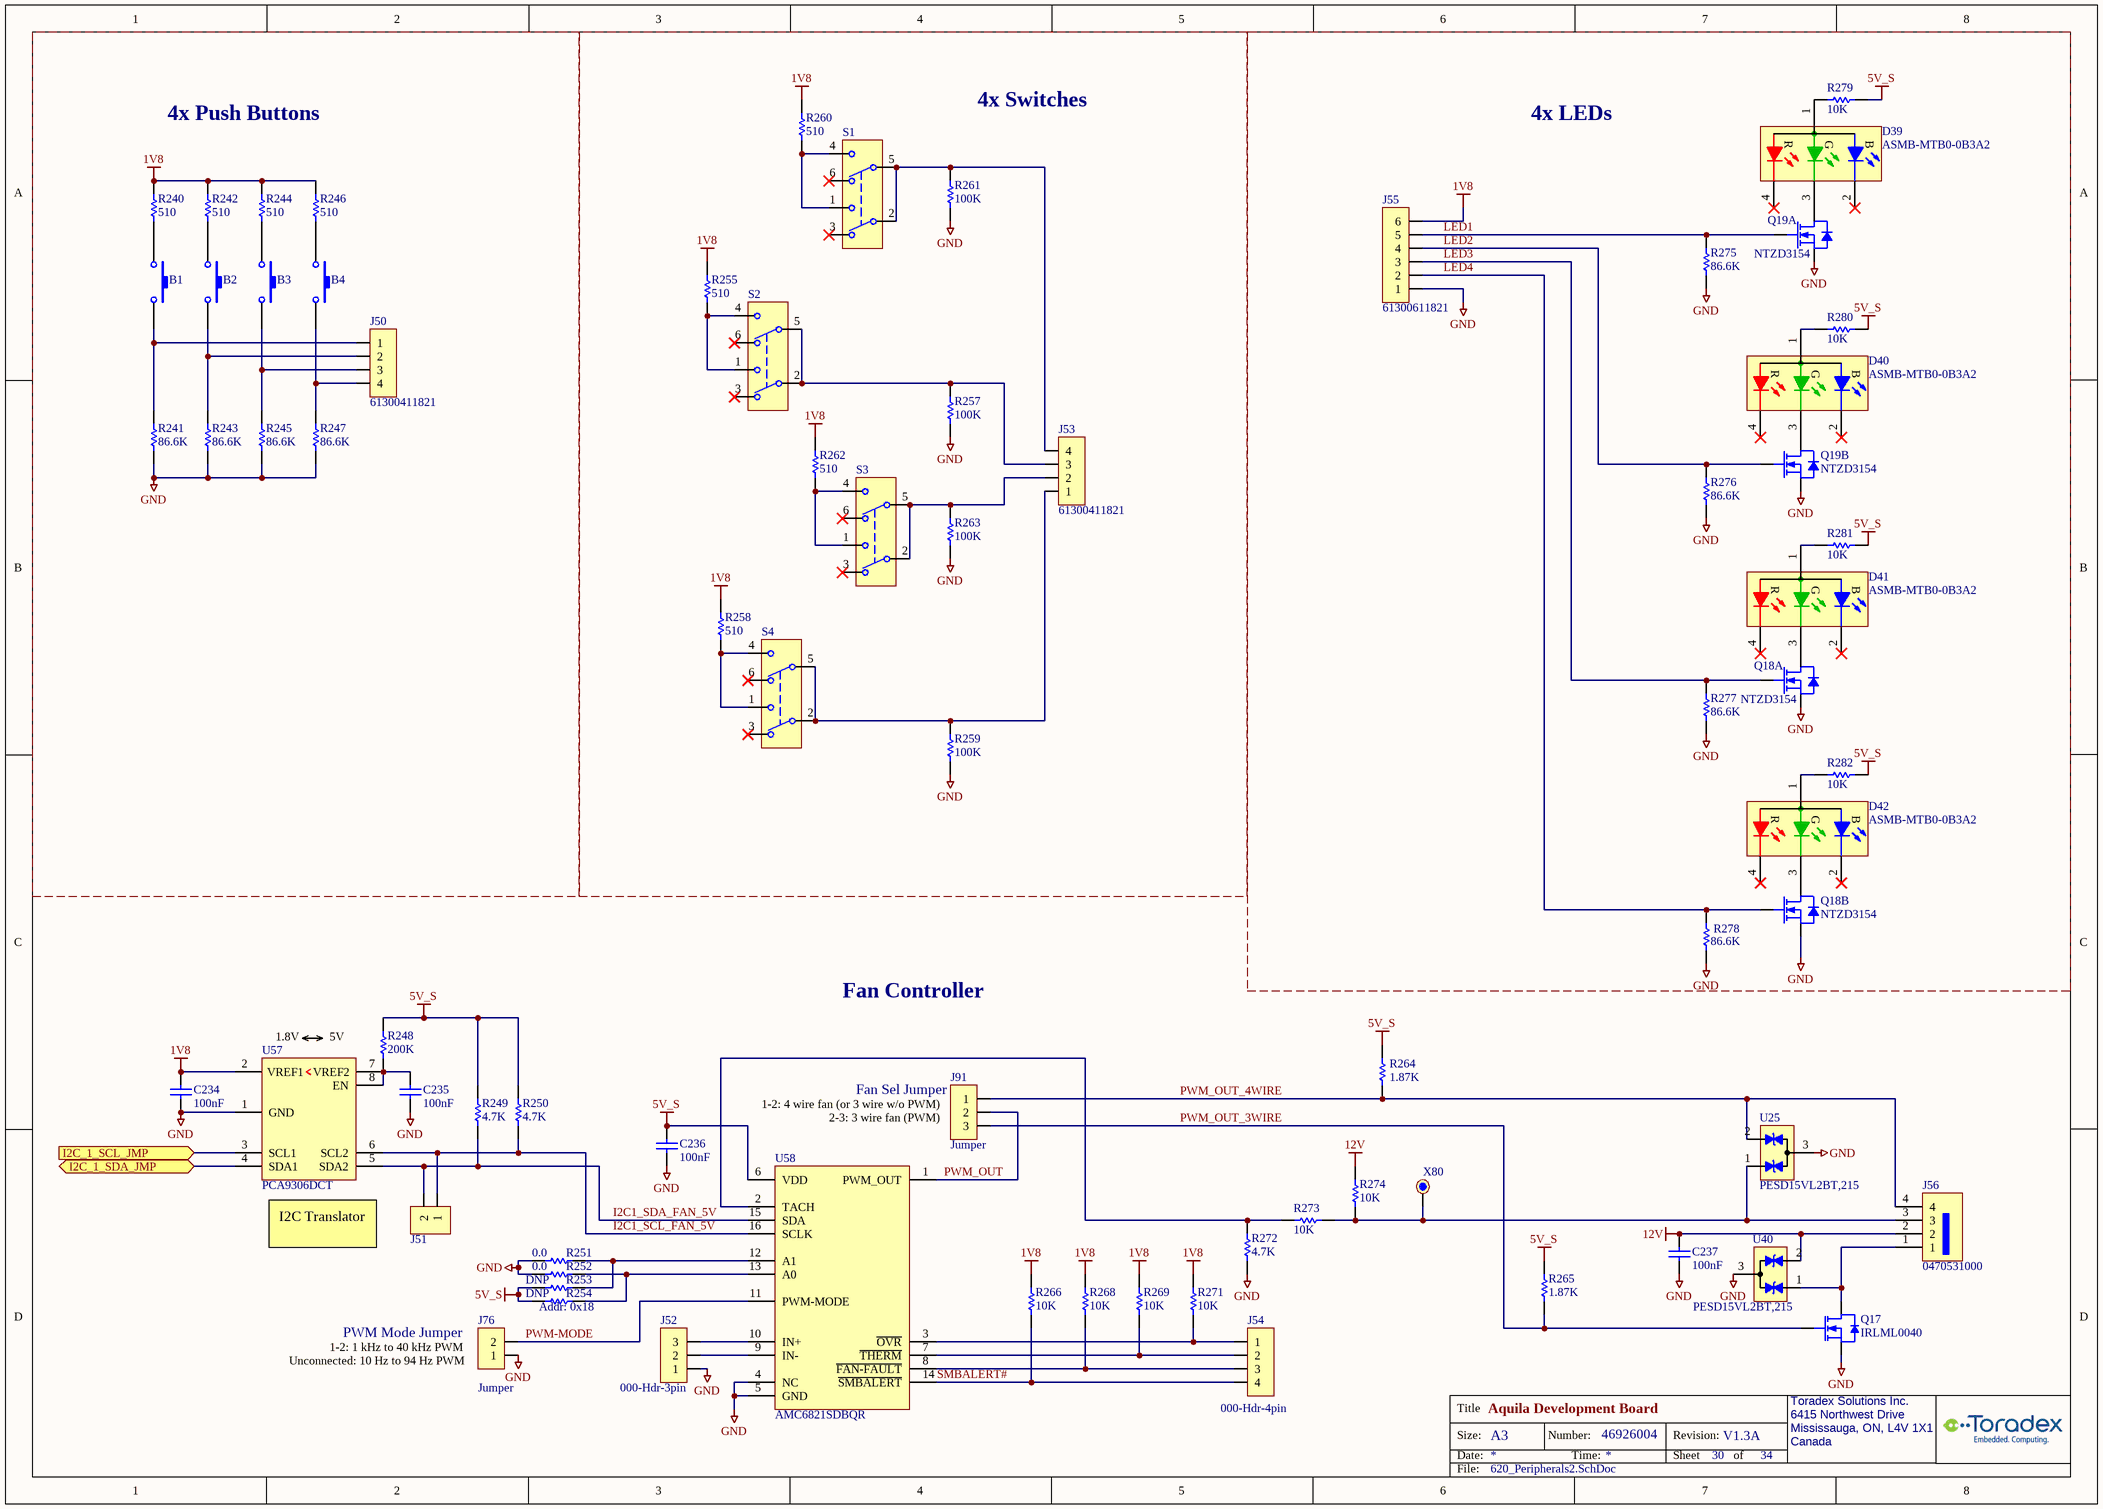
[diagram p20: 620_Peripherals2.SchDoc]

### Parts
B1  B3FS-1010P  [OMRONSW_B3FS-1010P]  (value not drawn)
B2  B3FS-1010P  [OMRONSW_B3FS-1010P]  (value not drawn)
B3  B3FS-1010P  [OMRONSW_B3FS-1010P]  (value not drawn)
B4  B3FS-1010P  [OMRONSW_B3FS-1010P]  (value not drawn)
C234  100nF  [C0402_CAPC1005L]
C235  100nF  [C0402_CAPC1005L]
C236  100nF  [C0402_CAPC1005L]
C237  100nF  [C0402_CAPC1005L]
D39  ASMB-MTB0-0B3A2  [4-PLCC]
D40  ASMB-MTB0-0B3A2  [4-PLCC]
D41  ASMB-MTB0-0B3A2  [4-PLCC]
D42  ASMB-MTB0-0B3A2  [4-PLCC]
J50  61300411821  [WURTH_61300411821]
J51  000-Hdr-2pin  [HDR1X2]  (value not drawn)  (no BOM)
J52  000-Hdr-3pin  [HDR1X3]  (no BOM)
J53  61300411821  [WURTH_61300411821]
J54  000-Hdr-4pin  [HDR1X4]  (no BOM)
J55  61300611821  [WURTH_61300611821]
J56  0470531000  [CONN_47053-1000_MOL]
J76  67996-200HLF  [CON_HDR1X2]  (value not drawn)
J91  68001-203HLF  [CON_HDR1X3]  (value not drawn)
Q17  IRLML0040  [SOT23]
Q18  NTZD3154  [SOT563]  (parts A,B of 2)
Q19  NTZD3154  [SOT563]  (parts A,B of 2)
R240  value 510  [R/0603]  (hidden comment: 0043-Res-0603-510ohm)
R241  value 86.6K  [R0402_RESC1005L]  (hidden comment: 1539-Res-0402-86.6k)
R242  value 510  [R/0603]  (hidden comment: 0043-Res-0603-510ohm)
R243  value 86.6K  [R0402_RESC1005L]  (hidden comment: 1539-Res-0402-86.6k)
R244  value 510  [R/0603]  (hidden comment: 0043-Res-0603-510ohm)
R245  value 86.6K  [R0402_RESC1005L]  (hidden comment: 1539-Res-0402-86.6k)
R246  value 510  [R/0603]  (hidden comment: 0043-Res-0603-510ohm)
R247  value 86.6K  [R0402_RESC1005L]  (hidden comment: 1539-Res-0402-86.6k)
R248  value 200K  [R0402_RESC1005L]  (hidden comment: 1540-Res-0402-200k)
R249  value 4.7K  [R0402_RESC1005L]  (hidden comment: 2233-Res-0402-4.7K)
R250  value 4.7K  [R0402_RESC1005L]  (hidden comment: 2233-Res-0402-4.7K)
R251  value 0.0  [R/0603]  (hidden comment: 0195-Res-0603-0.0ohm)
R252  value 0.0  [R/0603]  (hidden comment: 0195-Res-0603-0.0ohm)
R253  value DNP  [R/0603]  (hidden comment: 0000-Res-0603-DNP)
R254  value DNP  [R/0603]  (hidden comment: 0000-Res-0603-DNP)
R255  value 510  [R/0603]  (hidden comment: 0043-Res-0603-510ohm)
R257  value 100K  [R0402_RESC1005L]  (hidden comment: 1977-Res-0402-100K)
R258  value 510  [R/0603]  (hidden comment: 0043-Res-0603-510ohm)
R259  value 100K  [R0402_RESC1005L]  (hidden comment: 1977-Res-0402-100K)
R260  value 510  [R/0603]  (hidden comment: 0043-Res-0603-510ohm)
R261  value 100K  [R0402_RESC1005L]  (hidden comment: 1977-Res-0402-100K)
R262  value 510  [R/0603]  (hidden comment: 0043-Res-0603-510ohm)
R263  value 100K  [R0402_RESC1005L]  (hidden comment: 1977-Res-0402-100K)
R264  value 1.87K  [R0402_RESC1005L]  (hidden comment: 1536-Res-0402-1.87K)
R265  value 1.87K  [R0402_RESC1005L]  (hidden comment: 1536-Res-0402-1.87K)
R266  value 10K  [R0402_RESC1005L]  (hidden comment: 1572-Res-0402-10K)
R268  value 10K  [R0402_RESC1005L]  (hidden comment: 1572-Res-0402-10K)
R269  value 10K  [R0402_RESC1005L]  (hidden comment: 1572-Res-0402-10K)
R271  value 10K  [R0402_RESC1005L]  (hidden comment: 1572-Res-0402-10K)
R272  value 4.7K  [R0402_RESC1005L]  (hidden comment: 2233-Res-0402-4.7K)
R273  value 10K  [R0402_RESC1005L]  (hidden comment: 1572-Res-0402-10K)
R274  value 10K  [R0402_RESC1005L]  (hidden comment: 1572-Res-0402-10K)
R275  value 86.6K  [R0402_RESC1005L]  (hidden comment: 1539-Res-0402-86.6k)
R276  value 86.6K  [R0402_RESC1005L]  (hidden comment: 1539-Res-0402-86.6k)
R277  value 86.6K  [R0402_RESC1005L]  (hidden comment: 1539-Res-0402-86.6k)
R278  value 86.6K  [R0402_RESC1005L]  (hidden comment: 1539-Res-0402-86.6k)
R279  value 10K  [R0402_RESC1005L]  (hidden comment: 1572-Res-0402-10K)
R280  value 10K  [R0402_RESC1005L]  (hidden comment: 1572-Res-0402-10K)
R281  value 10K  [R0402_RESC1005L]  (hidden comment: 1572-Res-0402-10K)
R282  value 10K  [R0402_RESC1005L]  (hidden comment: 1572-Res-0402-10K)
S1  SLW-913535-2A-SMT  [SWITCH_SLW-913535-2A-SMT]  (value not drawn)
S2  SLW-913535-2A-SMT  [SWITCH_SLW-913535-2A-SMT]  (value not drawn)
S3  SLW-913535-2A-SMT  [SWITCH_SLW-913535-2A-SMT]  (value not drawn)
S4  SLW-913535-2A-SMT  [SWITCH_SLW-913535-2A-SMT]  (value not drawn)
U25  PESD15VL2BT,215  [SOT23_N]
U40  PESD15VL2BT,215  [SOT23_N]
U57  PCA9306DCT  [TSSO3x5-G8/X.35]
U58  AMC6821SDBQR  [16-SSOP_DBQ_TI]
X80  000-TestPoint  [TestPoint_1]  (value not drawn)

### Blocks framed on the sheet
4x Push Buttons: B1-B4 J50 R240-R247
4x Switches: J53 R255 R257-R263 S1-S4
4x LEDs: D39-D42 J55 Q18 Q19 R275-R282

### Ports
I2C_1_SCL_JMP (in), I2C_1_SDA_JMP (bidir)

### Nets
1V8: C234.2 J55.6 R240.1 R242.1 R244.1 R246.1 R255.1 R258.1 R260.1 R262.1 R266.1 R268.1 R269.1 R271.1 U57.2(VREF1)
5V_S: C236.2 R248.1 R249.1 R250.1 R253.1 R254.1 R264.1 R265.1 R279.2 R280.2 R281.2 R282.2 U58.6(VDD)
12V: C237.2 J56.2 R274.2 U40.2(K2)
GND: C234.1 C235.1 C236.1 C237.1 J52.1 J55.1 J76.1 Q17.2(S) Q18.1(S) Q18.4(S) Q19.1(S) Q19.4(S) R241.1 R243.1 R245.1 R247.1 R251.1 R252.1 R257.1 R259.1 R261.1 R263.1 R272.2 R275.1 R276.1 R277.1 R278.1 U25.3(CC) U40.3(CC) U57.1(GND) U58.4(NC) U58.5(GND)
I2C1_SCL_FAN_5V: J51.1 R250.2 U57.6(SCL2) U58.16(SCLK)
I2C1_SDA_FAN_5V: J51.2 R249.2 U57.5(SDA2) U58.15(SDA)
I2C_1_SCL_JMP: U57.3(SCL1) ; port I2C_1_SCL_JMP
I2C_1_SDA_JMP: U57.4(SDA1) ; port I2C_1_SDA_JMP
LED1: J55.5 Q19.2(G) R275.2
LED2: J55.4 Q19.5(G) R276.2
LED3: J55.3 Q18.2(G) R277.2
LED4: J55.2 Q18.5(G) R278.2
PWM-MODE: J76.2 U58.11(PWM-MODE)
PWM_OUT: J91.2 U58.1(PWM_OUT)
PWM_OUT_3WIRE: J91.3 Q17.1(G) R265.2
PWM_OUT_4WIRE: J56.4 J91.1 R264.2 U25.2(K2)
SMBALERT#: J54.4 R266.2 U58.14(~{SMBALERT})
NetB1_1: B1.1 R240.2
NetB1_3: B1.3 J50.1 R241.2
NetB2_1: B2.1 R242.2
NetB2_3: B2.3 J50.2 R243.2
NetB3_1: B3.1 R244.2
NetB3_3: B3.3 J50.3 R245.2
NetB4_1: B4.1 R246.2
NetB4_3: B4.3 J50.4 R247.2
NetC235_2: C235.2 R248.2 U57.7(VREF2) U57.8(EN)
NetD39_1: D39.1(A1) R279.1
NetD39_3: D39.3(A2) Q19.6(D)
NetD40_1: D40.1(A1) R280.1
NetD40_3: D40.3(A2) Q19.3(D)
NetD41_1: D41.1(A1) R281.1
NetD41_3: D41.3(A2) Q18.6(D)
NetD42_1: D42.1(A1) R282.1
NetD42_3: D42.3(A2) Q18.3(D)
NetJ52_2: J52.2 U58.9(IN-)
NetJ52_3: J52.3 U58.10(IN+)
NetJ53_1: J53.1 R259.2 S4.2(COMMON1) S4.5(COMMON2)
NetJ53_2: J53.2 R263.2 S3.2(COMMON1) S3.5(COMMON2)
NetJ53_3: J53.3 R257.2 S2.2(COMMON1) S2.5(COMMON2)
NetJ53_4: J53.4 R261.2 S1.2(COMMON1) S1.5(COMMON2)
NetJ54_1: J54.1 R271.2 U58.3(~{OVR})
NetJ54_2: J54.2 R269.2 U58.7(~{THERM})
NetJ54_3: J54.3 R268.2 U58.8(~{FAN-FAULT})
NetJ56_1: J56.1 Q17.3(D) U40.1(K1)
NetJ56_3: J56.3 R273.2 R274.1 U25.1(K1) X80.1
NetR251_2: R251.2 R253.2 U58.12(A1)
NetR252_2: R252.2 R254.2 U58.13(A0)
NetR255_2: R255.2 S2.1(NC1) S2.4(NC2)
NetR258_2: R258.2 S4.1(NC1) S4.4(NC2)
NetR260_2: R260.2 S1.1(NC1) S1.4(NC2)
NetR262_2: R262.2 S3.1(NC1) S3.4(NC2)
NetR272_1: R272.1 R273.1 U58.2(TACH)

Not connected (* = marked no-connect by the designer): D39 2(K1)* 4(K2)*; D40 2(K1)* 4(K2)*; D41 2(K1)* 4(K2)*; D42 2(K1)* 4(K2)*; S1 3(NO1)* 6(NO2)*; S2 3(NO1)* 6(NO2)*; S3 3(NO1)* 6(NO2)*; S4 3(NO1)* 6(NO2)*

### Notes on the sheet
- (near U57) 1.8V
- 5V
- Fan Controller
- (near J91) 1-2: 4 wire fan (or 3 wire w/o PWM)
- (near J91) 2-3: 3 wire fan (PWM)
- (near J91) Fan Sel Jumper
- (near J91) Jumper
- I2C Translator
- (near R254) Addr: 0x18
- (near J76) Unconnected: 10 Hz to 94 Hz PWM
- (near J76) 1-2: 1 kHz to 40 kHz PWM
- (near J76) PWM Mode Jumper
- (near J76) Jumper

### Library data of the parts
B1-B4 = 1511-Push Button: (-25 to 70 DegC) SWITCH TACTILE SPST-NO 0.05A 24V H:4.3mm Switch-PushButton; Mfr: Omron; PN: 1511; Alt: in bag: B3FS-1010; Note: similar to PN243 but taller
C234-C237 = 1566-Cap-0402-100nF/50V: as C99 on sheet 360_Ethernet2
D39-D42 = 1775-ASMB-MTB0-0B3A2: (-40 to 100 DegC) LED RGB DIFFUSED 4PLCC SMD; Mfr: Broadcom; PN: 1775; Alt: PN 0813
J50 J53 = 2191-Conn-Hdr 1x4 2.54MM F: (-40 to 125 DegC) CONN HEADER FEMALE 1x4 4POS 2.54MM TH; Mfr: Wurth Electronics; PN: 2191
J51 = 000-Hdr-2pin: as J28 on sheet 360_Ethernet2
J52 = 000-Hdr-3pin: as J35 on sheet 360_Ethernet2
J54 = 000-Hdr-4pin: Header, 4-Pin; Note: PCB footprint only, no parts to buy or assemble
J55 = 2189-Conn-Hdr 1x6 2.54MM F: (-40 to 125 DegC) CONN HEADER FEMALE 1x6 6POS  2.54MM TH; Mfr: Wurth Electronics; PN: 2189
J56 = 2220-Conn-Hdr 4POS 2.54MM: (-40 to 80 DegC) CONN HEADER VERT 4POS 2.54MM - 1 Wall Shrouded; Mfr: Molex; MfrNo: 47053-1000; PN: 2220
J76 = 1250-Conn-Hdr-1x2 TH Vert: (-40 to 85 DegC) CONN HDR VERT 1x2 2pos 2.54mm 0.1in Gold no-shroud; Mfr: Amphenol FCI; PN: 1250
J91 = 2539-Conn-Hdr-1x3 TH Vert: (-65 to 125 DegC) CONN HDR VERT 3x1 3pos 2.54mm 0.1in Gold no-shroud; Mfr: Amphenol ICC / FCI; PN: 2539
Q17 = 0910-IRLML0040TRPBF: (-55 to 150 DegC) MOSFET N-CH 40V 3.6A SOT-23-3 Ron typ 60mohm@5V, ---@3V; Mfr: Infineon Technologies; PN: 910; Alt: SI2318CDS-T1-GE3, TSM2318CX RFG
Q18 Q19 = 1146-NTZD3154NT1G: as Q15 on sheet 360_Ethernet2
R240 R242 R244 R246 R255 R258 R260 R262 = 0043-Res-0603-510ohm: (-55 to 155 DegC) RES 510 OHM 1/10W 1% 0603 SMD; Mfr: Yageo; MfrNo: RC0603FR-07510RL; Alt: RHM510HCT-ND; Alt2: RMCF0603FT510RCT-ND; PN: 43; TR: 311-510HRTR-ND
R241 R243 R245 R247 R275-R278 = 1539-Res-0402-86.6k: (-55 to 155 DegC AEC) RES 86.6K OHM 1% 1/16W 100ppm 0402; Mfr: Stackpole Electronics; MfrNo: RMCF0402FT86K6; Alt: AC0402FR-0786K6L,RK73H1ETTP8662F,ERJ-2RKF8662X; PN: 1539
R248 = 1540-Res-0402-200k: (-55 to 155 DegC AEC) RES 200K OHM 1% 1/16W 100ppm 0402; Mfr: Stackpole Electronics; MfrNo: RMCF0402FT200K; Alt: AC0402FR-07200KL,AC0402FR-7W200KL,ERJ-2RKF2003X; PN: 1540
R249 R250 R272 = 2233-Res-0402-4.7K: as R172 on sheet 360_Ethernet2
R251 R252 = 0195-Res-0603-0.0ohm: as R199 on sheet 410_M2_KeyM
R253 R254 = 0000-Res-0603-DNP: RES 0603
R257 R259 R261 R263 = 1977-Res-0402-100K: as R63 on sheet 360_Ethernet2
R264 = 1536-Res-0402-1.87K: as R202 on sheet 410_M2_KeyM
R265 = 1536-Res-0402-1.87K: as R175 on sheet 360_Ethernet2
R266 R268 R269 R271 R273 R274 = 1572-Res-0402-10K: as R152 on sheet 360_Ethernet2
R279-R282 = 1572-Res-0402-10K: (-55 to 155 DegC AEC) RES 10K OHM 1% 1/16W 100ppm 0402; MfrNo: RMCF0402FT10K0; Mfr: Stackpole Electronics; PN: 1572; Alt: AC0402FR-0710KL,AC0402FR-1310KL,CRGCQ0402F10K
S1-S4 = 2693-Slide Switch-DPDT VERT SMT: (-20 to 70 DegC) Slide switch DPDT 12V 100mA SMT 9.1x6.9mm VERT SLIDE; Mfr: Same Sky (CUI); PN: 2693
U25 U40 = 2239-PESD15VL2BT,215: (-65 to 150 DegC) TVS DIODE 2-CH 15VWM 44VC ESD:30KV TO236AB; Mfr: Nexperia; PN: 2239
U57 = 0972-PCA9306DCT: (-40 to 85 DegC) IC TRANSLTR BIDIRECTIONAL I2C SM8; MfrNo: PCA9306DCTR; Mfr: Texas Instruments; PN: 972
U58 = 2219-AMC6821SDBQR: (-40 to 125 DegC) IC TEMP MONTR/PWM FANCTRL 3.3-5V, I2C 16SSOP; Mfr: Texas Instruments; PN: 2219
X80 = 000-TestPoint: as X54-X57 on sheet 360_Ethernet2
